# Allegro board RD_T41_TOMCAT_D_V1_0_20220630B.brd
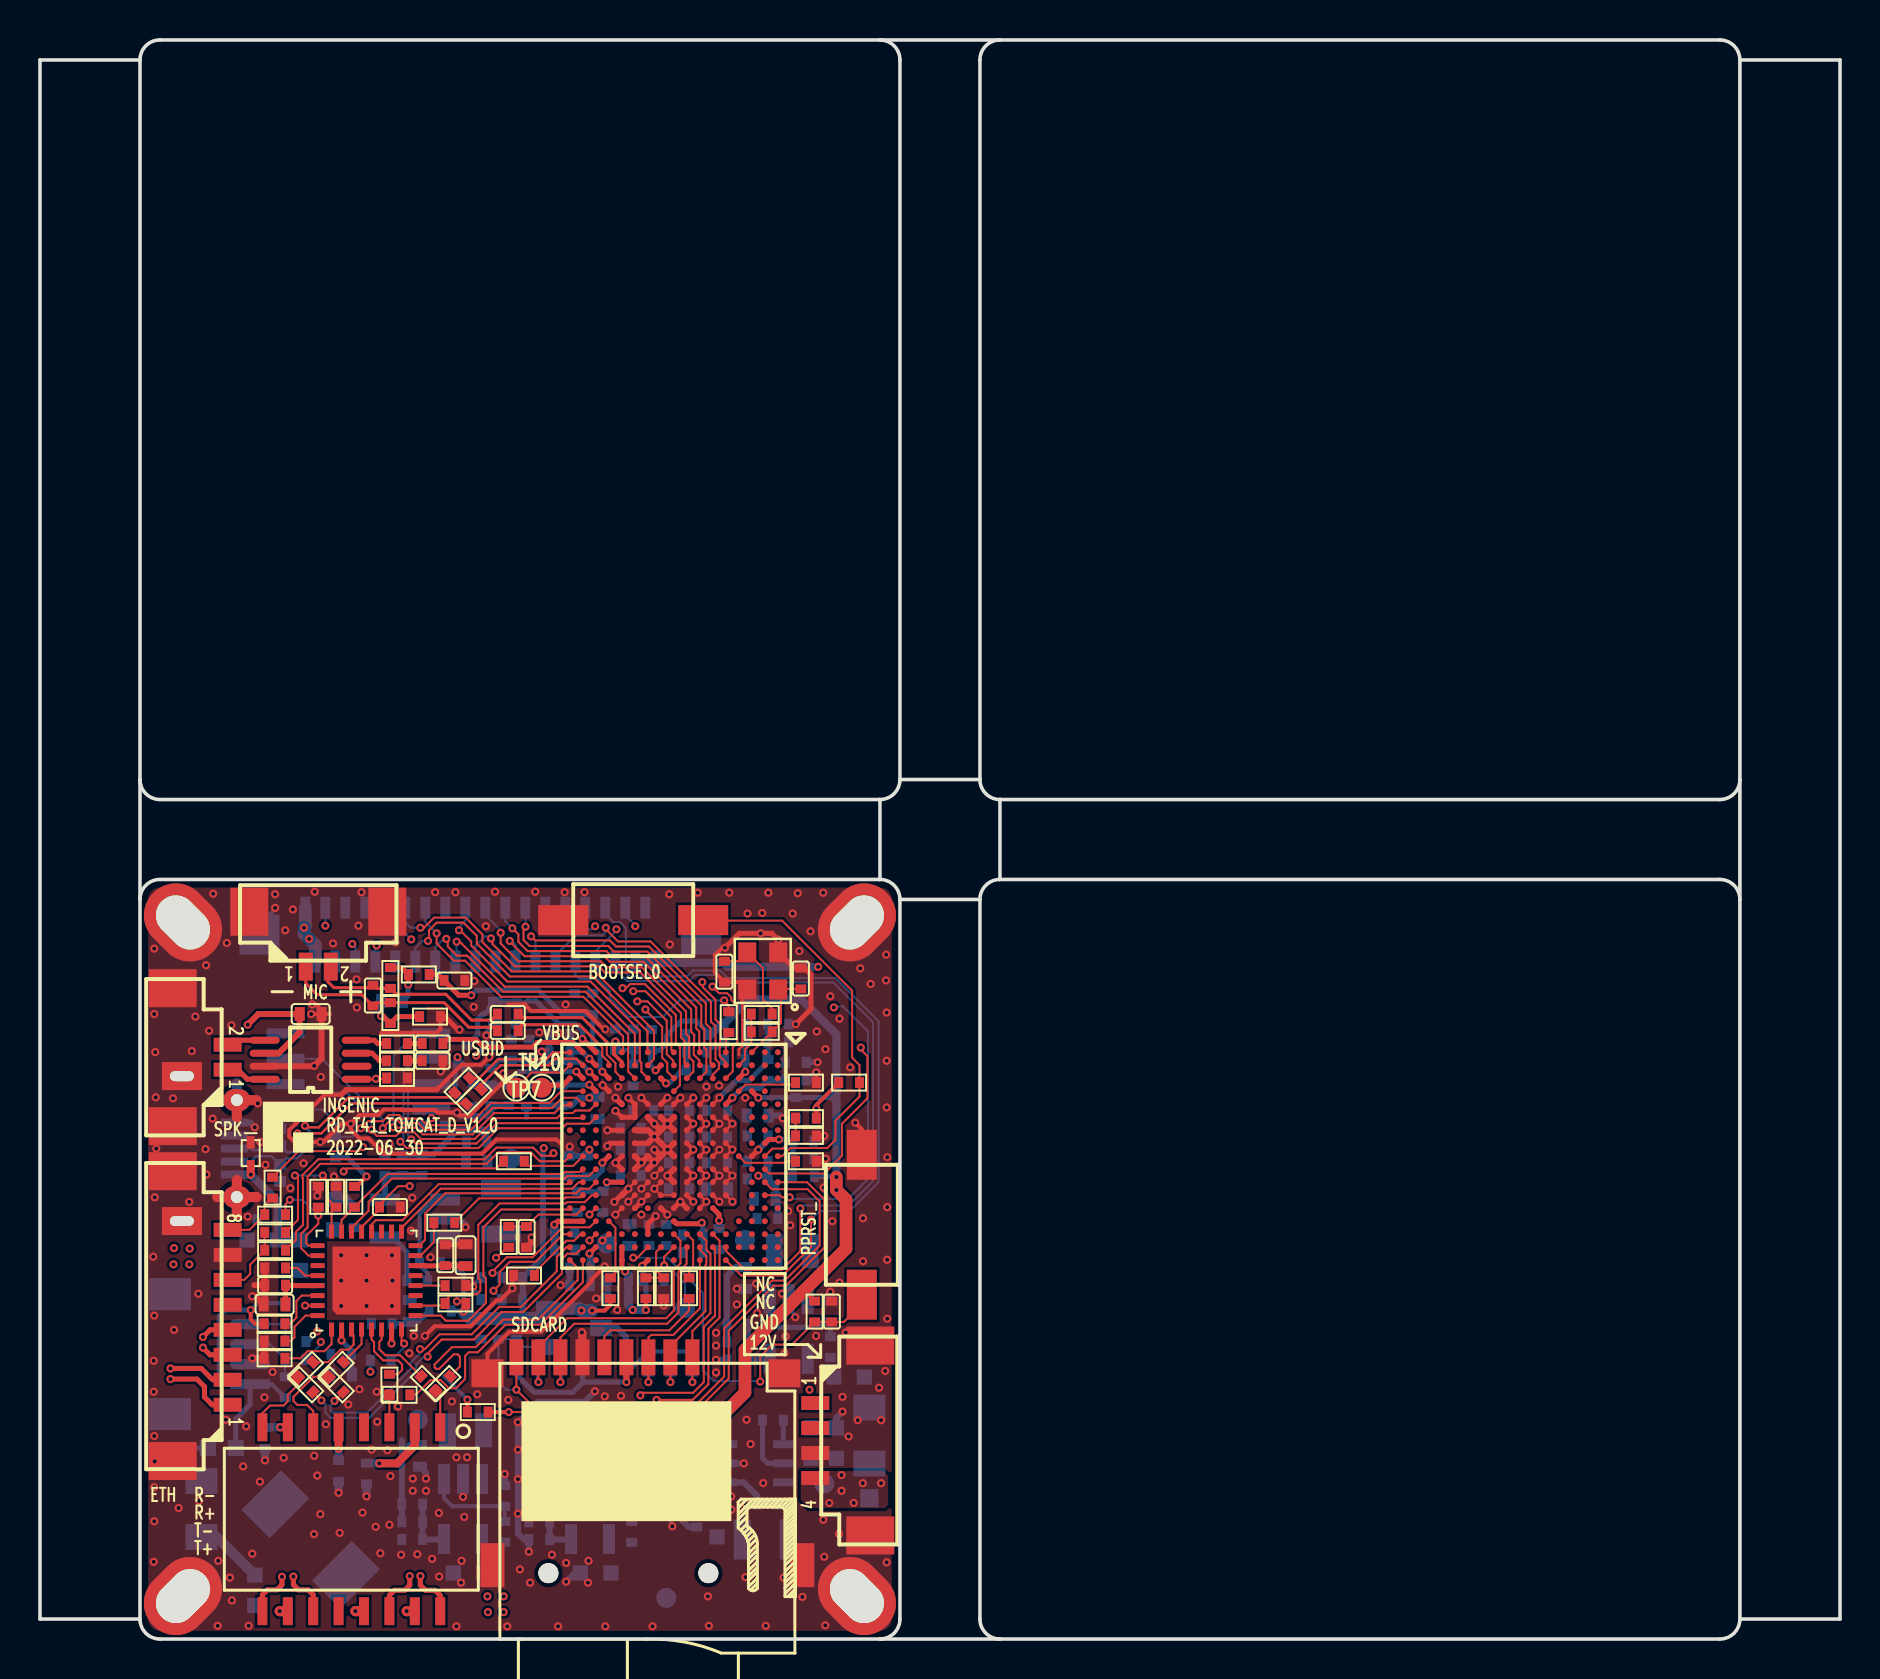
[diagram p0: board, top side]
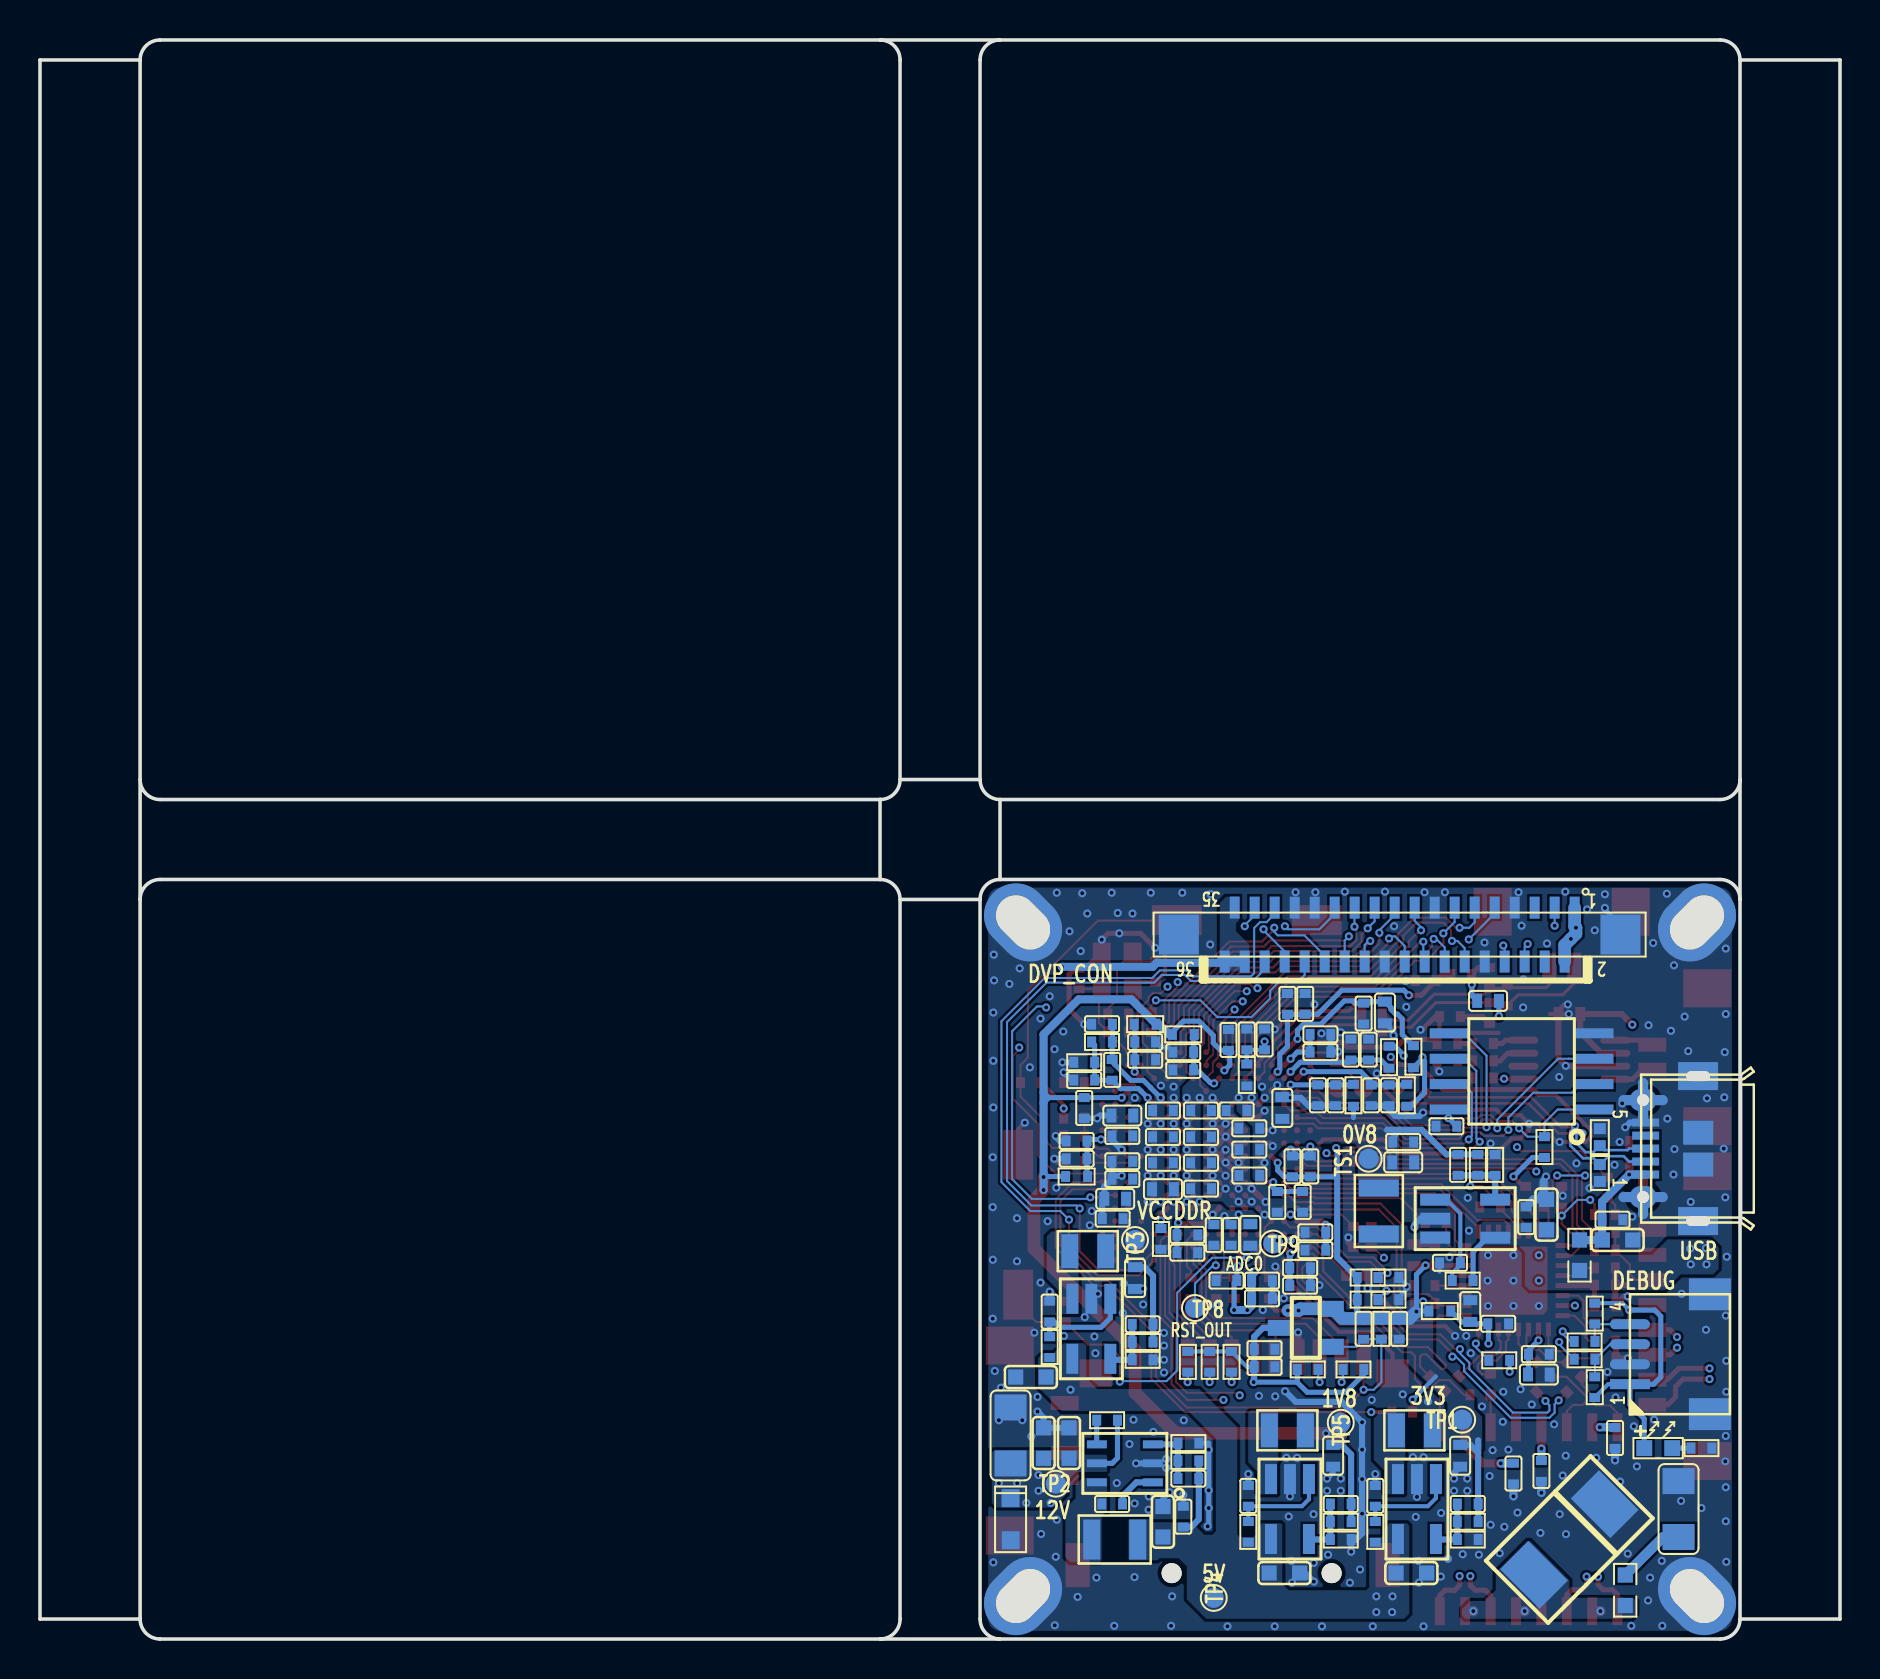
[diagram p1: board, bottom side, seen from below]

Outline 90.01 x 80 mm; copper layers: TOP, L2_GND, L3_PWR, BOTTOM. Coordinates in mm from the lower left corner of the outline.
Outline path: 5,1 0,1 0,79 5,79 ; 5,1 5,37 ; 5,1 arc(5.29,0.29) 6,0 42,0 ; 5,79 5,43 ; 5,79 arc(5.29,79.71) 6,80 42,80 ; 5,43 5,37 ; 5,43 arc(5.29,42.29) 6,42 42,42 ; 5,37 arc(5.29,37.71) 6,38 42,38 ; 42,42 42,38 ; 42,42 arc(42.71,42.29) 43,43 ; 42,38 arc(42.71,37.71) 43,37 ; 42,80 arc(42.71,79.71) 43,79 43,43 ; 42,80 48,80 ; 43,37 43,1 arc(42.71,0.29) 42,0 ; 43,37 47,37 ; 42,0 48,0 ; 48,0 arc(47.29,0.29) 47,1 47,37 ; 48,0 84,0 arc(84.71,0.29) 85,1 ; 43,43 47,43 ; 48,80 arc(47.29,79.71) 47,79 47,43 ; 48,80 84,80 arc(84.71,79.71) 85,79 ; 47,43 arc(47.29,42.29) 48,42 ; 47,37 arc(47.29,37.71) 48,38 ; 48,38 48,42 ; 48,38 84,38 arc(84.71,37.71) 85,37 ; 48,42 48.01,41.99 ; 48,42 84,42 arc(84.71,42.29) 85,43 ; 85,79 85,43 ; 85,79 90.01,79 90.01,1 85,1 ; 85,37 85,43 ; 85,37 85,1

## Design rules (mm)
net group DP_RD: nets RD_N RD_P
net group DP_TD: nets TD_N TD_P
net group DP_TRXN0: nets TRXN0 TRXP0
net group DP_TRXN1: nets TRXN1 TRXP1
net group MDI_R: nets MDI_RN MDI_RP
net group MDI_T: nets MDI_TN MDI_TP
net group MICNL: nets MICNL N16707590
net group MICPL: nets MICPL N16712105
net group RJ45_RX: nets RX+ RX-
net group RJ45_TX: nets TX+ TX-
net group USB0PN: nets N16707578 USB0PN
net group USB0PP: nets N16707574 USB0PP
net group POW: nets AVDD33 CSI_VCC08 CSI_VCC18 DDR_VREF DVDD1V2OUT MICBIAS USB_AVD08 USB_AVD18 USB_AVD33 VDDMSC0
nets with their own width: min track width 0.203; nets GND VCC_3V3

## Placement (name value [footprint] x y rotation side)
C1  22uF/25V-1206  [C1206]  41.47 10.19 90 bottom
C2  10uF/10V-0603  [C0603]  21.43 3.3 180 bottom
C3  100nF/10V  [C0402]  23.24 7.16 90 bottom
C4  22pF/50V  [C0402]  18.61 6.76 0 bottom
C5  10uF/6.3V  [C0402_E]  19 9.17 270 bottom
C6  10nF/25V  [C0402]  36.39 6.76 0 bottom
C7  10uF/25V-0603  [C0603]  39.82 9.8 90 bottom
C8  10uF/25V-0603  [C0603]  38.55 9.8 90 bottom
C9  22pF/50V  [C0402]  34.87 15.75 0 bottom
C10  22pF/50V  [C0402]  32.58 8.03 0 bottom
C11  10uF/10V-0603  [C0603]  33.85 5.87 90 bottom
C12  100nF/10V  [C0402]  32.84 6.12 90 bottom
C13  10uF/10V-0603  [C0603]  40.46 13.11 0 bottom
C14  100nF/10V  [C0402]  39.52 16.38 90 bottom
C15  10uF/6.3V  [C0402_E]  35.25 18.06 270 bottom
C16  22pF/50V  [C0402]  24.96 6.76 0 bottom
C17  10uF/6.3V  [C0402_E]  25.35 9.17 270 bottom
C18  10uF/10V-0603  [C0603]  27.78 3.3 180 bottom
C19  10uF/10V-0603  [C0603]  14.68 21.23 90 bottom
C20  100nF/10V  [C0402]  15.69 21.11 90 bottom
C21  10uF/6.3V  [C0402_E]  21.84 23.85 180 bottom
C22  100nF/6.3V  [C0402]  21.84 24.87 180 bottom
C23  22pF/50V  [C0402]  19.1 23.72 90 bottom
C24  100nF/6.3V  [C0402]  35.89 23.01 0 bottom
C25  10uF/6.3V  [C0402_E]  36.24 22.02 0 bottom
C26  100nF/6.3V  [C0402]  35.89 23.9 0 bottom
C27  100nF/6.3V  [C0402]  35.89 25.17 0 bottom
C28  10uF/6.3V  [C0402_E]  35.89 26.19 0 bottom
C29  1uF/6.3V  [C0402]  32.84 28.47 0 bottom
C30  1uF/6.3V  [C0402]  34.74 29.87 180 bottom
C31  1uF/6.3V  [C0402]  26.87 21.87 270 bottom
C32  10uF/6.3V  [C0402_E]  33.85 22.5 180 bottom
C33  100nF/6.3V  [C0402]  36.37 21.03 0 bottom
C34  10nF/6.3V  [C0402]  33.85 23.83 180 bottom
C35  100nF/6.3V  [C0402]  33.85 25.12 180 bottom
C36  1uF/6.3V  [C0402]  22.55 27.2 270 bottom
C37  100nF/6.3V  [C0402]  33.85 26.44 180 bottom
C38  1uF/6.3V  [C0402]  28.9 17.04 180 bottom
C39  1uF/6.3V  [C0402]  27.38 23.65 90 bottom
C40  100nF/6.3V  [C0402]  36.39 28.47 90 bottom
C41  4.7uF/6.3V  [C0402]  36.9 30.76 0 bottom
C42  100nF/6.3V  [C0402]  37.79 27.97 180 bottom
C43  10uF/6.3V  [C0402_E]  27.89 26.57 90 bottom
C44  10uF/6.3V  [C0402_E]  29.49 20.22 270 bottom
C45  100nF/6.3V  [C0402]  29.54 24.49 0 bottom
C46  100nF/6.3V  [C0402]  29.54 25.55 0 bottom
C47  100nF/6.3V  [C0402]  30.17 26.44 0 bottom
C48  100nF/6.3V  [C0402]  31.95 26.44 180 bottom
C49  100nF/6.3V  [C0402]  31.95 23.83 180 bottom
C50  100nF/6.3V  [C0402]  31.95 22.53 180 bottom
C51  1uF/6.3V  [C0402]  32.64 20.22 180 bottom
C52  10nF/6.3V  [C0402]  31.95 25.12 180 bottom
C53  10nF/6.3V  [C0402]  31.31 20.22 270 bottom
C54  1uF/6.3V  [C0402]  38.17 24.03 0 bottom
C55  10nF/6.3V  [C0402]  29.54 23.19 0 bottom
C56  10uF/6.3V  [C0402_E]  17.6 31.93 0 bottom
C57  1uF/6.3V  [C0402]  26.23 19.46 0 bottom
C58  100nF/6.3V  [C0402]  26.23 20.35 0 bottom
C59  1uF/6.3V  [C0402]  27 18.57 180 bottom
C60  100nF/6.3V  [C0402]  27 17.68 180 bottom
C61  100nF/6.3V  [C0402]  24.33 20.12 90 top
C62  100nF/10V  [C0402]  29.59 7.16 90 bottom
C63  100nF/6.3V  [C0402]  34.74 28.98 180 bottom
C64  100nF/6.3V  [C0402]  38.17 24.92 0 bottom
C65  100nF/6.3V  [C0402]  23.82 31.29 270 bottom
C66  10uF/6.3V  [C0402_E]  22.75 31.34 270 bottom
C67  100nF/6.3V  [C0402]  23.39 31.27 180 top
C68  100nF/6.3V  [C0402]  23.39 30.43 180 top
C69  4.7uF/6.3V  [C0402]  25.98 30.25 180 bottom
C70  100nF/6.3V  [C0402]  25.98 29.36 180 bottom
C71  1uF/6.3V  [C0402]  25.22 27.2 270 bottom
C72  100nF/6.3V  [C0402]  26.11 27.2 270 bottom
C73  100nF/6.3V  [C0402]  23.44 27.2 270 bottom
C74  1uF/6.3V  [C0402]  23.57 29.49 90 bottom
C75  100nF/6.3V  [C0402]  24.46 29.49 90 bottom
C76  100nF/6.3V  [C0402]  28.9 17.93 180 bottom
C78  4.7uF/6.3V  [C0402]  26.74 31.78 90 bottom
C79  100nF/6.3V  [C0402]  27.63 31.78 90 bottom
C80  12pF/50V  [C0402]  38.05 33.05 270 top
C81  100nF/6.3V  [C0402]  19.68 25.65 180 bottom
C82  12pF/50V  [C0402]  34.22 33.39 90 top
C83  100nF/6.3V  [C0402]  30.68 17.93 0 bottom
C84  1uF/6.3V  [C0402]  29.66 30 90 bottom
C85  100nF/6.3V  [C0402]  28.77 30 90 bottom
C86  100nF/6.3V  [C0402]  32.84 29.36 0 bottom
C87  100nF/6.3V  [C0402]  30.58 29.97 90 bottom
C88  100nF/6.3V  [C0402]  37.79 26.57 270 bottom
C89  100nF/6.3V  [C0402]  26.49 23.65 90 bottom
C90  100nF/6.3V  [C0402]  32.64 19.33 180 bottom
C91  4.7uF/6.3V  [C0402]  22.04 15.52 270 bottom
C92  100nF/6.3V  [C0402]  23.82 15.52 270 bottom
C93  4.7uF/6.3V  [C0402]  28.77 14.5 180 bottom
C94  100nF/6.3V  [C0402]  28.77 13.61 180 bottom
C95  10uF/10V-0603  [C0603]  11.12 19.96 180 bottom
C96  100nF/25V  [C0402]  16.33 8.28 90 bottom
C97  100nF/25V  [C0402]  14.93 8.41 90 bottom
C98  100nF/25V  [C0402]  11.25 10.06 90 bottom
C99  10uF/6.3V  [C0402_E]  21.28 19.2 90 top
C100  100nF/6.3V  [C0402]  20.27 19.2 90 top
C101  10uF/6.3V  [C0402_E]  15.06 13.23 180 bottom
C102  100nF/6.3V  [C0402]  15.06 14.25 180 bottom
C103  10uF/6.3V  [C0402_E]  11.73 16.74 180 top
C104  100nF/6.3V  [C0402]  11.76 17.7 180 top
C105  100pF/50V  [C0402]  16.65 32.19 90 top
C106  3.3nF/50V  [C0402]  19.63 28.93 0 top
C107  3.3nF/50V  [C0402]  19.63 29.79 0 top
C108  10uF/6.3V  [C0402_E]  13.53 31.27 0 top
C110  4.7uF/6.3V  [C0402]  20.72 32.94 0 top
C111  1uF/6.3V  [C0402]  39.59 16.38 90 top
C112  100nF/10V  [C0402]  19.5 18.82 0 bottom
C113  100nF/6.3V  [C0402]  30.45 20.22 270 bottom
C114  100nF/6.3V  [C0402]  28.14 21.87 270 bottom
C119  100nF/10V  [C0402]  11.38 20.98 180 bottom
C125  100nF/6.3V  [C0402]  17.5 21.62 0 top
C126  1nF/2KV-1206  [C1206]  8.07 6.5 270 bottom
C127  10uF/6.3V  [C0402_E]  18.49 16.41 90 bottom
C128  100nF/6.3V  [C0402]  17.09 15.77 180 bottom
D1  BZT52C12S  [SOD323]  41.47 5.99 90 bottom
D2  LED Red  [D0603_LED]  9.09 9.55 180 bottom
D3  LXES1UTAA1-157  [DFN1006]  12.01 25.11 90 bottom
D4  P3100SC  [SMB]  13.53 4.98 315 bottom
D5  LXES1UTAA1-157  [DFN1006]  12.01 23.32 270 bottom
D6  ESD5451X  [ESD0402]  10.54 24.31 270 top
FB1  1000ohm/250mA  [FB0402]  38.17 23.14 0 bottom
FB2  1000ohm/250mA  [FB0402]  20.01 16.41 0 bottom
FB3  1000ohm/250mA  [FB0402]  34.74 30.76 180 bottom
FB4  1000ohm/250mA  [FB0402]  24.33 27.2 90 bottom
FB5  1000ohm/250mA  [FB0402]  21.66 27.2 90 bottom
FB6  1000ohm/250mA  [FB0402]  22.55 29.11 270 bottom
FB7  1000ohm/250mA  [FB0402]  21.33 29.13 90 bottom
FB8  1000ohm/250mA  [FB0402]  29.66 28.22 270 bottom
FB9  1000ohm/250mA  [FB0402]  32.84 30.25 0 bottom
H1  MHOBL  [MHOLE_3D0X2D0]  7.15 35.85 90 top
H2  MHOBL  [MHOLE_3D0X2D0]  40.85 2.15 90 top
H3  MHOBL  [MHOLE_3D0X2D0]  7.15 2.15 0 top
H4  MHOBL  [MHOLE_3D0X2D0]  40.85 35.85 0 top
J1  CON4 1.25mm LT  [CON4-1D25-LT]  40.97 9.93 90 top
J2  MICROSD_TF  [TFCARD]  30.37 13.9 0 top
J3  CON36 0.5mm LT  [FPC-CON36-0D5-LT]  22.02 35.24 0 bottom
J4  MICRO USB  [MICROUSB_B_NJ5P]  9.72 24.54 270 bottom
J5  CON8 1.25mm LT  [CON8-1D25-LT]  7.18 16.15 270 top
J6  CON2 1.25mm LT  [CON2-1D25-LT]  13.92 35.84 180 top
J7  CON2 1.25mm LT  [CON2-1D25-LT]  7.18 29.11 270 top
J8  CON4 1.0mm WT  [CON4-1D0-WT]  8 14.25 90 bottom
L1  2.2uH/1.3A-2016  [L2016]  21.28 10.44 0 bottom
L2  4.7uH/1.4A-2520  [L2520]  36.27 4.98 180 bottom
L3  2.2uH/1.3A-2016  [L2016]  37.61 19.41 0 bottom
L4  2.2uH/2.2A-2520  [L2520]  23.06 21.41 90 bottom
L5  2.2uH/1.3A-2016  [L2016]  27.63 10.44 0 bottom
NOREF  -  []  12.87 25.59 0 top
NOREF#2  -  []  5.32 37.73 0 top
NOREF#3  -  []  41.27 158.18 0 top
NOREF#4  -  []  6 0 90 top
NOREF#5  -  []  5 1 0 top
NOREF#6  -  []  -189.11 -122.58 0 top
NOREF#7  -  []  -41.62 136.12 0 top
Q1  WPM3401  [SOT23]  26.71 15.57 90 bottom
R1  100K  [R0402]  23.24 5.36 90 bottom
R2  150K/1%  [R0402]  18.61 5.87 180 bottom
R3  33.2K/1%  [R0402]  18.61 4.98 0 bottom
R4  100K  [R0402]  36.65 10.95 0 bottom
R5  100K  [R0402]  39.52 14.61 90 bottom
R6  200K/1%  [R0402]  32.58 8.92 0 bottom
R7  150K/1%  [R0402]  34.87 14.86 180 bottom
R8  27K/1%  [R0402]  32.58 9.8 0 bottom
R9  100K/1%  [R0402]  34.87 13.97 0 bottom
R10  100K  [R0402]  18.87 17.93 0 bottom
R11  100K  [R0402]  29.59 5.36 90 bottom
R13  2.2R/1%  [R0402]  13.28 12.73 135 top
R14  1K  [R0402]  6.93 9.55 180 bottom
R15  100K/1%  [R0402]  36.9 29.87 180 bottom
R16  240R/1%  [R0402]  33.96 20.02 270 bottom
R17  100K/1%  [R0402]  37.79 28.85 180 bottom
R18  240R/1%  [R0402]  38.3 23.9 0 top
R19  33R  [R0402]  20.21 20.83 180 top
R20  1K  [R0402]  30.3 17.55 90 top
R21  33R  [R0402]  38.3 27.84 180 top
R22  10K  [R0402]  14.78 24.61 270 bottom
R23  1M  [R0402]  36.09 30.38 0 top
R24  33R  [R0402]  36.09 31.27 180 top
R25  33R  [R0402]  32.46 17.55 90 top
R26  2.49K/1%  [R0402]  24.2 18.19 180 top
R27  1K  [R0402]  22.58 16.98 0 bottom
R28  2.2R/1%  [R0402]  14.8 12.73 135 top
R29  100K  [R0402]  26.62 13.49 180 bottom
R30  100K  [R0402]  30.43 13.87 270 bottom
R31  100K  [R0402]  24.33 13.49 0 bottom
R32  100K  [R0402]  32.61 13.87 270 bottom
R33  100K  [R0402]  31.52 13.87 270 bottom
R34  100K  [R0402]  22.93 15.52 270 bottom
R35  2.2R/1%  [R0402]  13.28 13.49 225 top
R36  2.2R/1%  [R0402]  14.8 13.49 225 top
R37  10K  [R0402]  15.72 22.12 270 top
R39  2.2R/1%  [R0402]  17.47 12.73 270 top
R40  2.2R/1%  [R0402]  19.42 12.78 315 top
R41  2.49K/1%  [R0402]  11.73 14.05 180 top
R44  10K  [R0402]  20.77 16.79 180 top
R46  10K  [R0402]  11.76 18.57 0 top
R47  0R  [R0402]  11.73 14.91 0 top
R48  1.1K  [R0402]  17.52 31.32 270 top
R49  1.1K  [R0402]  19.5 31.14 180 top
R50  10K  [R0402]  17.85 28.07 0 top
R51  1.1K  [R0402]  17.52 33.07 270 top
R52  68K/1%  [R0402]  17.85 28.93 0 top
R53  68K/1%  [R0402]  17.85 29.79 0 top
R55  100K  [R0402]  40.46 27.84 180 top
R56  100K  [R0402]  38.3 26.06 0 top
R57  10K  [R0402]  12.26 12.6 90 bottom
R58  10K  [R0402]  12.26 16.28 270 bottom
R59  100K  [R0402]  38.3 25.17 180 top
R60  33R  [R0402]  12.77 14.88 0 bottom
R61  33R  [R0402]  12.77 14 0 bottom
R62  100K  [R0402]  38.73 16.38 270 top
R63  100K/1%  [R0402]  18.11 23.72 90 bottom
R64  300K/1%  [R0402]  17.24 23.72 90 bottom
R65  10K  [R0402]  23.62 18.08 0 bottom
R66  33R  [R0402]  23.69 23.9 0 top
R67  33R  [R0402]  34.44 30.86 270 top
R68  10K  [R0402]  28.52 17.55 270 top
R69  10K  [R0402]  23.62 16.98 0 bottom
R70  10K  [R0402]  21.89 11.35 180 top
R71  1K  [R0402]  22.58 18.08 0 bottom
R72  2.2R/1%  [R0402]  17.98 12.22 180 top
R73  2.2R/1%  [R0402]  20.14 12.78 225 top
R74  300R  [R0402]  11.76 19.46 180 top
R75  300R  [R0402]  11.63 22.58 270 top
R76  300R  [R0402]  11.76 21.23 0 top
R77  300R  [R0402]  11.76 20.35 0 top
R78  1K  [R0402]  31.19 17.55 90 top
R81  1.1K  [R0402]  18.94 33.25 180 top
R85  0R-0603  [R0603]  13.03 19.2 270 bottom
R86  200K/1%  [R0402]  24.96 5.87 180 bottom
R87  10K  [R0402]  17.04 13.94 0 bottom
R88  10K  [R0402]  14.8 22.12 270 top
R89  10K  [R0402]  13.92 22.12 270 top
R92  10K  [R0402]  20.77 17.68 180 top
R93  75R/1%-0603  [R0603]  10.74 2.44 270 bottom
R94  10K  [R0402]  11.73 15.77 180 top
R98  100K/1%  [R0402]  24.96 4.98 0 bottom
R99  0R  [R0402]  23.44 20.12 270 top
R100  2.2R/5%  [R0402]  21.11 27.7 225 top
R101  2.2R/5%  [R0402]  21.69 27.14 225 top
SW1  KEY2_SMD  [SW2_SMD]  29.66 35.97 0 top
SW2  KEY2_SMD  [SW2_SMD]  41.09 20.73 270 top
TP1  1mm_SMD  [TEST_SMD]  18.89 10.97 180 bottom
TP2  1mm_SMD  [TEST_SMD]  39.21 7.77 180 bottom
TP3  1mm_SMD  [TEST_SMD]  35.25 19.96 90 bottom
TP4  1mm_SMD  [TEST_SMD]  31.31 2.06 90 bottom
TP5  1mm_SMD  [TEST_SMD]  24.96 10.82 90 bottom
TP7  1mm_SMD  [TEST_SMD]  23.82 27.58 0 top
TP8  1mm_SMD  [TEST_SMD]  32.25 16.56 180 bottom
TP9  1mm_SMD  [TEST_SMD]  28.34 19.79 180 bottom
TP10  1mm_SMD  [TEST_SMD]  25.09 27.58 0 top
TS1  1mm_SMD  [TEST_SMD]  23.57 24.03 90 bottom
U1  LN5058  [SOT23-5]  21.15 6.5 0 bottom
U2  ETA8120  [SOT23-6]  35.76 8.79 0 bottom
U3  LN5058  [SOT23-5]  37.44 15.52 0 bottom
U4  LN5058  [SOT23-5]  27.5 6.5 0 bottom
U5  ETA3409  [SOT23-5]  18.74 21.03 270 bottom
U6  T41 BGA232  [BGA232_0D65_T41]  31.7 24.16 270 top
U7  GD25Q127CSIG  [WSOP8_1D27]  15.92 28.4 0 bottom
U8  SZ18201  [QFN32_0D5_SZ18201]  16.33 17.93 90 top
U9  FC1680C  [QFP16_1D27]  15.57 5.99 270 top
U10  CS8302M  [MSOP8_0D65]  13.53 28.98 90 top
Y1  24M 2016  [CRY_2D5X2D0]  36.14 33.43 90 top

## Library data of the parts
C1-C66 C69-C76 C78-C108 C110-C114 C119 C125-C128 = CAP
C67 C68 = CAP: signal model: CAP_C0402_100NF/6.3V_100nF/6.3V
D1 = DIODE_WY
D2 = LED_1
D3 D5 D6 = ESD
D4 = P3100
FB1-FB9 = BEAD
H1-H4 = MHOLE1
J1 = CON_4x1
J2 = MMC_SD
J3 = FPCCON_18X2
J4 = MICROUSB_0
J5 = CON_8x1
J6 J7 = CON_2X1
J8 = CON_4X1
L1-L5 = INDUCTOR
Q1 = P_MOS
R1-R11 R13-R37 R39-R41 R44 R46-R53 R55-R78 R81 R85-R89 R92-R94 R98 R99 = RES
R100 R101 = RES: signal model: RES_R0402_2.2R/5%_2.2R/5%
SW1 SW2 = PUSHBUTTON
TP1-TP5 TP7-TP10 TS1 = TP
U1 U3-U5 = SY8088
U2 = SY8120
U6 = T41_BGA232
U7 = SPI_NOR
U8 = SZ18201
U9 = FC1680C
U10 = CS8302
Y1 = XTAL_P4

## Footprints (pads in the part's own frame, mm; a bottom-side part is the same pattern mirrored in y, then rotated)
BGA232_0D65_T41
  round 0.3 smd: A1(-5.2,5.2) A2(-4.55,5.2) A3(-3.9,5.2) A5(-2.6,5.2) A7(-1.3,5.2) A9(0,5.2) A11(1.3,5.2) A13(2.6,5.2) A15(3.9,5.2) A16(4.55,5.2) A17(5.2,5.2) B1(-5.2,4.55) B2(-4.55,4.55) B3(-3.9,4.55) B4(-3.25,4.55) B5(-2.6,4.55) B6(-1.95,4.55) B7(-1.3,4.55) B8(-0.65,4.55) B9(0,4.55) B10(0.65,4.55) B11(1.3,4.55) B12(1.95,4.55) B13(2.6,4.55) B14(3.25,4.55) B15(3.9,4.55) B16(4.55,4.55) B17(5.2,4.55) C1(-5.2,3.9) C2(-4.55,3.9) C3(-3.9,3.9) C4(-3.25,3.9) C5(-2.6,3.9) C6(-1.95,3.9) C7(-1.3,3.9) C8(-0.65,3.9) C9(0,3.9) C10(0.65,3.9) C11(1.3,3.9) C12(1.95,3.9) C13(2.6,3.9) C14(3.25,3.9) C15(3.9,3.9) C16(4.55,3.9) C17(5.2,3.9) D2(-4.55,3.25) D3(-3.9,3.25) D4(-3.25,3.25) D9(0,3.25) D14(3.25,3.25) D15(3.9,3.25) D16(4.55,3.25) E1(-5.2,2.6) E2(-4.55,2.6) E3(-3.9,2.6) E5(-2.6,2.6) E6(-1.95,2.6) E7(-1.3,2.6) E8(-0.65,2.6) E9(0,2.6) E10(0.65,2.6) E11(1.3,2.6) E12(1.95,2.6) E15(3.9,2.6) E16(4.55,2.6) E17(5.2,2.6) F2(-4.55,1.95) F3(-3.9,1.95) F5(-2.6,1.95) F6(-1.95,1.95) F7(-1.3,1.95) F8(-0.65,1.95) F9(0,1.95) F10(0.65,1.95) F11(1.3,1.95) F12(1.95,1.95) F13(2.6,1.95) F15(3.9,1.95) F16(4.55,1.95) G1(-5.2,1.3) G2(-4.55,1.3) G3(-3.9,1.3) G5(-2.6,1.3) G6(-1.95,1.3) G7(-1.3,1.3) G8(-0.65,1.3) G9(0,1.3) G10(0.65,1.3) G11(1.3,1.3) G12(1.95,1.3) G13(2.6,1.3) G15(3.9,1.3) G16(4.55,1.3) G17(5.2,1.3) H2(-4.55,0.65) H3(-3.9,0.65) H5(-2.6,0.65) H6(-1.95,0.65) H7(-1.3,0.65) H8(-0.65,0.65) H9(0,0.65) H10(0.65,0.65) H11(1.3,0.65) H12(1.95,0.65) H13(2.6,0.65) H15(3.9,0.65) H16(4.55,0.65) J1(-5.2,0) J2(-4.55,0) J3(-3.9,0) J4(-3.25,0) J5(-2.6,0) J6(-1.95,0) J7(-1.3,0) J8(-0.65,0) J9(0,0) J10(0.65,0) J11(1.3,0) J12(1.95,0) J13(2.6,0) J14(3.25,0) J15(3.9,0) J16(4.55,0) J17(5.2,0) K2(-4.55,-0.65) K3(-3.9,-0.65) K5(-2.6,-0.65) K6(-1.95,-0.65) K7(-1.3,-0.65) K8(-0.65,-0.65) K9(0,-0.65) K10(0.65,-0.65) K11(1.3,-0.65) K12(1.95,-0.65) K13(2.6,-0.65) K15(3.9,-0.65) K16(4.55,-0.65) L1(-5.2,-1.3) L2(-4.55,-1.3) L3(-3.9,-1.3) L5(-2.6,-1.3) L6(-1.95,-1.3) L7(-1.3,-1.3) L8(-0.65,-1.3) L9(0,-1.3) L10(0.65,-1.3) L11(1.3,-1.3) L12(1.95,-1.3) L13(2.6,-1.3) L15(3.9,-1.3) L16(4.55,-1.3) L17(5.2,-1.3) M2(-4.55,-1.95) M3(-3.9,-1.95) M5(-2.6,-1.95) M6(-1.95,-1.95) M7(-1.3,-1.95) M8(-0.65,-1.95) M9(0,-1.95) M10(0.65,-1.95) M11(1.3,-1.95) M12(1.95,-1.95) M13(2.6,-1.95) M15(3.9,-1.95) M16(4.55,-1.95) N1(-5.2,-2.6) N2(-4.55,-2.6) N3(-3.9,-2.6) N5(-2.6,-2.6) N6(-1.95,-2.6) N7(-1.3,-2.6) N8(-0.65,-2.6) N9(0,-2.6) N10(0.65,-2.6) N11(1.3,-2.6) N12(1.95,-2.6) N13(2.6,-2.6) N15(3.9,-2.6) N16(4.55,-2.6) N17(5.2,-2.6) P2(-4.55,-3.25) P3(-3.9,-3.25) P4(-3.25,-3.25) P9(0,-3.25) P14(3.25,-3.25) P15(3.9,-3.25) P16(4.55,-3.25) R1(-5.2,-3.9) R2(-4.55,-3.9) R3(-3.9,-3.9) R4(-3.25,-3.9) R5(-2.6,-3.9) R6(-1.95,-3.9) R7(-1.3,-3.9) R8(-0.65,-3.9) R9(0,-3.9) R10(0.65,-3.9) R11(1.3,-3.9) R12(1.95,-3.9) R13(2.6,-3.9) R14(3.25,-3.9) R15(3.9,-3.9) R16(4.55,-3.9) R17(5.2,-3.9) T1(-5.2,-4.55) T2(-4.55,-4.55) T3(-3.9,-4.55) T4(-3.25,-4.55) T5(-2.6,-4.55) T6(-1.95,-4.55) T7(-1.3,-4.55) T8(-0.65,-4.55) T9(0,-4.55) T10(0.65,-4.55) T11(1.3,-4.55) T12(1.95,-4.55) T13(2.6,-4.55) T14(3.25,-4.55) T15(3.9,-4.55) T16(4.55,-4.55) T17(5.2,-4.55) U1(-5.2,-5.2) U2(-4.55,-5.2) U3(-3.9,-5.2) U5(-2.6,-5.2) U7(-1.3,-5.2) U9(0,-5.2) U11(1.3,-5.2) U13(2.6,-5.2) U15(3.9,-5.2) U16(4.55,-5.2) U17(5.2,-5.2)
C0402
  rect 0.45x0.55 smd: 1(-0.52,0) 2(0.52,0)
C0402_E
  rect 0.5x0.7 smd: 1(-0.545,0) 2(0.545,0)
C0603
  rect 0.76x0.76 smd: 1(-0.762,0) 2(0.762,0)
C1206
  rect 1.3x1.6 smd: 1(-1.4,0) 2(1.4,0)
CON2-1D25-LT
  rect 0.7x1.4 smd: 1(0.625,2.2) 2(-0.625,2.2)
  rect 1.9x2.4 smd: 3(-3.45,-0.55) 4(3.45,-0.55)
CON4-1D0-WT
  rect 0.5x2 smd: 1(-1.5,2.5)
  oval 0.5x2 smd: 2(-0.5,2.5) 3(0.5,2.5) 4(1.5,2.5)
  rect 1.6x2.1 smd: 5(3,-1.5) 6(-3,-1.5)
CON4-1D25-LT
  rect 0.7x1.4 smd: 1(1.875,2.2) 2(0.625,2.2) 3(-0.625,2.2) 4(-1.875,2.2)
  rect 1.9x2.4 smd: 5(-4.75,-0.55) 6(4.75,-0.55)
CON8-1D25-LT
  rect 0.7x1.4 smd: 1(4.435,2.2) 2(3.185,2.2) 3(1.935,2.2) 4(0.685,2.2) 5(-0.565,2.2) 6(-1.815,2.2) 7(-3.065,2.2) 8(-4.315,2.2)
  rect 1.9x2.4 smd: 9(-7.25,-0.55) 10(7.25,-0.55)
CRY_2D5X2D0
  rect 1x0.9 smd: 1(-0.925,-0.775) 2(0.925,-0.775) 3(0.925,0.775) 4(-0.925,0.775)
D0603_LED
  rect 0.8x0.8 smd: 1(-0.7,0) 2(0.7,0)
DFN1006
  rect 0.55x0.6 smd: 1(0.425,0) 2(-0.425,0)
ESD0402
  rect 0.62x0.4 smd: 1(-0.54,0)
  rect 0.5x0.4 smd: 2(0.6,0)
FB0402
  rect 0.45x0.55 smd: 1(-0.55,0) 2(0.55,0)
FPC-CON36-0D5-LT
  rect 0.5x1.1 smd: 1(-8.75,-1.35) 2(-8.25,1.35) 3(-7.75,-1.35) 4(-7.25,1.35) 5(-6.75,-1.35) 6(-6.25,1.35) 7(-5.75,-1.35) 8(-5.25,1.35) 9(-4.75,-1.35) 10(-4.25,1.35) 11(-3.75,-1.35) 12(-3.25,1.35) 13(-2.75,-1.35) 14(-2.25,1.35) 15(-1.75,-1.35) 16(-1.25,1.35) 17(-0.75,-1.35) 18(-0.25,1.35) 19(0.25,-1.35) 20(0.75,1.35) 21(1.25,-1.35) 22(1.75,1.35) 23(2.25,-1.35) 24(2.75,1.35) 25(3.25,-1.35) 26(3.75,1.35) 27(4.25,-1.35) 28(4.75,1.35) 29(5.25,-1.35) 30(5.75,1.35) 31(6.25,-1.35) 32(6.75,1.35) 33(7.25,-1.35) 34(7.75,1.35) 35(8.25,-1.35) 36(8.75,1.35)
  rect 2x2 smd: 37(-11.04,0) 38(11.04,0)
L2016
  rect 0.85x1.7 smd: 1(0.9,0) 2(-0.9,0)
L2520
  rect 0.85x2 smd: 1(-1.15,0) 2(1.15,0)
MHOLE_3D0X2D0
  oval 4.2x3.2 hole 3x2 rot 45: 1(0,0)
MICROUSB_B_NJ5P
  rect 0.4x1.35 smd: 1(1.3,0) 2(0.65,0) 3(0,0) 4(-0.65,0) 5(-1.3,0)
  rect 1.4x2 hole 0.5x1.2: 6(3.625,2.625) 7(-3.625,2.625)
  oval 1.1x1.35 hole 0.6: 8(-2.425,-0.125) 9(2.425,-0.125)
  rect 1.2x1.5 smd: 10(-0.8,2.625) 11(0.8,2.625)
MSOP8_0D65
  oval 0.35x1.5 smd: 1(-0.975,-2.3) 2(-0.325,-2.3) 3(0.325,-2.3) 4(0.975,-2.3) 5(0.975,2.3) 6(0.325,2.3) 7(-0.325,2.3) 8(-0.975,2.3)
QFN32_0D5_SZ18201
  rect 0.7x0.25 smd: 1(-2.45,1.75) 2(-2.45,1.25) 3(-2.45,0.75) 4(-2.45,0.25) 5(-2.45,-0.25) 6(-2.45,-0.75) 7(-2.45,-1.25) 8(-2.45,-1.75) 17(2.45,-1.75) 18(2.45,-1.25) 19(2.45,-0.75) 20(2.45,-0.25) 21(2.45,0.25) 22(2.45,0.75) 23(2.45,1.25) 24(2.45,1.75)
  rect 0.25x0.7 smd: 9(-1.75,-2.45) 10(-1.25,-2.45) 11(-0.75,-2.45) 12(-0.25,-2.45) 13(0.25,-2.45) 14(0.75,-2.45) 15(1.25,-2.45) 16(1.75,-2.45) 25(1.75,2.45) 26(1.25,2.45) 27(0.75,2.45) 28(0.25,2.45) 29(-0.25,2.45) 30(-0.75,2.45) 31(-1.25,2.45) 32(-1.75,2.45)
  custom 0.85x0.85 smd: 33(0,0)
QFP16_1D27
  rect 1.4x0.5 smd: 1(-4.6,4.445) 2(-4.6,3.175) 3(-4.6,1.905) 4(-4.6,0.635) 5(-4.6,-0.635) 6(-4.6,-1.905) 7(-4.6,-3.175) 8(-4.6,-4.445) 9(4.6,-4.445) 10(4.6,-3.175) 11(4.6,-1.905) 12(4.6,-0.635) 13(4.6,0.635) 14(4.6,1.905) 15(4.6,3.175) 16(4.6,4.445)
R0402
  rect 0.45x0.55 smd: 1(-0.52,0) 2(0.52,0)
R0603
  rect 0.76x0.76 smd: 1(-0.762,0) 2(0.762,0)
SMB
  rect 2x2.8 smd: 1(2.5,0) 2(-2.5,0)
SOD323
  rect 0.9x0.9 smd: 1(-1.05,0) 2(1.05,0)
SOT23
  rect 0.8x1.1 smd: 1(-0.95,-1.35) 2(0.95,-1.35) 3(0,1.35)
SOT23-5
  rect 0.6x1.5 smd: 1(-0.95,-1.5) 2(0,-1.5) 3(0.95,-1.5) 4(0.95,1.5) 5(-0.95,1.5)
SOT23-6
  rect 1x0.4 smd: 1(-1.4,0.95) 2(-1.4,0) 3(-1.4,-0.95) 4(1.4,-0.95) 5(1.4,0) 6(1.4,0.95)
SW2_SMD
  rect 2.5x1.5 smd: 1(-3.5,0) 2(3.5,0)
TEST_SMD
  round 1 smd: 1(0,0)
TFCARD
  round 1 hole 1 unplated: (-4.95,-10.6) (3.05,-10.6)
  rect 0.7x1.8 smd: 1(2.25,0.2) 2(1.15,0.2) 3(0.05,0.2) 4(-1.05,0.2) 5(-2.15,0.2) 6(-3.25,0.2) 7(-4.35,0.2) 8(-5.45,0.2) 9(-6.55,0.2)
  rect 1.6x1.4 smd: 10(-8,-0.6) 13(6.85,-0.6)
  rect 1.2x2.2 smd: 11(-7.75,-10.2) 12(7.75,-10.2)
WSOP8_1D27
  rect 1.9x0.5 smd: 1(-3.645,1.905) 2(-3.645,0.635) 3(-3.645,-0.635) 4(-3.645,-1.905) 5(3.645,-1.905) 6(3.645,-0.635) 7(3.645,0.635) 8(3.645,1.905)

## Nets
AVDD33: C127.1 C128.1 FB2.1 U8.7(AVDD33_1)
AVDDL_REG: C59.1 C60.1 U6.R16(AVDDL_REG)
DVDD1V2OUT: C57.1 C58.1 U6.T14(DVDD1V2OUT)
GND: C1.2 C2.2 C3.2 C5.2 C7.2 C8.2 C11.2 C12.2 C13.2 C14.2 C15.2 C17.2 C18.2 C19.2 C20.2 C21.2 C22.2 C24.2 C25.2 C26.2 C27.2 C28.2 C29.2 C30.2 C31.2 C32.2 C33.2 C34.2 C35.2 C36.2 C37.2 C38.2 C39.2 C41.2 C42.1 C43.2 C44.2 C45.2 C46.2 C47.2 C48.2 C49.2 C50.2 C51.2 C52.2 C53.2 C54.2 C55.2 C57.2 C58.2 C59.2 C60.2 C61.1 C62.2 C63.2 C64.2 C65.2 C66.2 C69.2 C70.2 C71.2 C72.2 C73.2 C74.2 C75.2 C76.2 C78.2 C79.2 C80.1 C81.1 C82.1 C83.2 C84.2 C85.2 C86.2 C87.2 C88.2 C89.2 C90.2 C91.2 C93.2 C94.2 C95.2 C96.1 C97.1 C98.1 C99.2 C100.2 C101.2 C102.2 C103.2 C104.2 C106.2 C108.2 C110.2 C111.2 C112.2 C113.2 C114.2 C119.2 C125.2 C126.1 C127.2 C128.2 D1.1 D3.1(ANODE) D4.2 D5.1(ANODE) D6.1(ANODE) H1.1(A) H2.1(A) H3.1(A) H4.1(A) J1.3 J1.5(S1) J1.6(S2) J2.6(VSS2) J2.10(GND_2) J2.11(GND_1) J2.12(PAD1) J2.13(PAD2) J3.7 J3.10 J3.15 J3.20 J3.27 J3.29 J3.37(S1) J3.38(S2) J4.5(GND1) J4.6(GND2) J4.7(GND3) J4.8(GND4) J4.9(GND5) J4.10(GND6) J4.11(GND7) J5.7 J5.9(S1) J5.10(S2) J6.3(S1) J6.4(S2) J7.3(S1) J7.4(S2) J8.2 J8.5(S1) J8.6(S2) R3.1 R8.1 R9.1 R14.2 R16.2 R17.1 R18.2 R21.1 R26.2 R27.1 R41.2 R46.1 R47.1 R49.1 R50.2 R59.1 R64.2 R71.1 R78.1 R88.1 R89.1 R92.1 R98.1 SW1.1 SW2.1 U1.2(GND) U2.2(GND) U3.2(GND) U4.2(GND) U5.2(GND) U6.C9(DDRPLL_VSSA) U6.G5(PLL_AVSS) U6.G6(VSS1) U6.G7(VSS2) U6.G8(VSS3) U6.G9(VSS4) U6.G10(VSS5) U6.G11(VSS6) U6.G12(VSS7) U6.G13(VSS8) U6.J6(VSS9) U6.J7(VSS10) U6.J8(VSS11) U6.J9(VSS12) U6.J10(VSS13) U6.J11(VSS14) U6.J12(VSS15) U6.K6(VSS16) U6.K7(VSS17) U6.K8(VSS18) U6.K9(VSS19) U6.K10(VSS20) U6.K11(VSS21) U6.K12(VSS22) U6.L6(VSS23) U6.L7(VSS24) U6.L8(VSS25) U6.L9(VSS26) U6.L10(VSS27) U6.L11(VSS28) U6.L12(VSS29) U6.M7(VSS30) U6.M8(VSS31) U6.M9(VSS32) U6.M10(VSS33) U6.M11(VSS34) U6.M12(VSS35) U6.M13(VSS36) U6.N5(CSI_VSSA) U6.N12(VSS37) U6.N13(SADC_AGND) U6.P4(CODEC_AVSS) U7.4(GND) U8.33(GND) U10.7(GND) Y1.2 Y1.4
VBUS: TP10.1 U6.U3(VBUS)
VCC_0V8: C21.1 C22.1 C23.2 C43.1 C44.1 C45.1 C46.1 C47.1 C48.1 C49.1 C50.1 C52.1 C53.1 C55.1 C113.1 FB4.1 FB8.2 L4.2 R63.2 TS1.1 U6.H5(VDD1) U6.H6(VDD2) U6.H7(VDD3) U6.H8(VDD4) U6.H9(VDD5) U6.H10(VDD6) U6.H11(VDD7) U6.H12(VDD8) U6.H13(VDD9) U6.J5(VDD10) U6.J13(VDD11) U6.K5(VDD12) U6.K13(VDD13) U6.L5(VDD14) U6.L15(VDD_RTC) U6.M5(VDD15) U6.M6(VDD16) U6.N6(VDD17) U6.N7(VDD18) U6.N8(VDD19) U6.N9(VDD20) U6.N10(VDD21)
VCC_1V8: C16.1 C17.1 C31.1 C38.1 C76.1 C83.1 C87.1 C88.1 C114.1 FB1.2 FB3.2 FB5.1 FB7.1 FB9.2 L5.2 R20.1 R62.1 R86.2 TP5.1 U6.C4(VDDIO2) U6.K2(VDDIO18_2) U6.L17(VDDIO_RTC) U6.N11(VDDIO18_1) U6.N16(SADC_VREFP) U6.N17(SADC_AVDD)
VCC_3V3: C4.1 C5.1 C39.1 C51.1 C81.2 C89.1 C90.1 C91.1 C92.1 C99.1 C100.1 D2.1(ANODE) FB2.2 FB6.1 J3.1 J3.2 J8.1 L1.2 Q1.2(SOURCE) R2.2 R22.2 R34.1 R37.1 R44.1 R55.2 R56.2 R57.1 R58.1 R65.2 R68.2 R69.2 R70.2 R87.1 R94.2 TP1.1 U6.J14(VDDIO33_2) U6.P9(VDDIO33_1) U7.8(VCC) U8.14(DVDD33_1)
VCC_5V: C2.1 C10.1 C11.1 C12.1 C13.1 C18.1 C19.1 C20.1 C108.1 J3.34 J3.35 J3.36 L2.2 R1.1 R5.1 R6.1 R10.1 R11.1 R85.2 TP4.1 U1.4(IN) U3.4(IN) U4.4(IN) U5.4(IN) U10.6(VDD)
VCC_12V: C1.1 C7.1 C8.1 D1.2 J1.4 R4.1 TP2.1 U2.5(VIN)
VCC_DDR: C9.1 C15.1 C24.1 C25.1 C26.1 C27.1 C28.1 C32.1 C33.1 C34.1 C35.1 C37.1 C40.2 C41.1 L3.2 R7.2 R15.2 TP3.1 U6.E6(VDDMEM1) U6.E7(VDDMEM2) U6.E8(VDDMEM3) U6.E9(VDDMEM4) U6.E10(VDDMEM5) U6.E11(VDDMEM6) U6.E12(VDDMEM7) U6.F5(DDRVDD1) U6.F6(DDRVDD2) U6.F7(DDRVDD3) U6.F8(DDRVDD4) U6.F9(DDRVDD5) U6.F10(DDRVDD6) U6.F11(DDRVDD7) U6.F12(DDRVDD8)
VDDMSC0: C93.1 C94.1 J2.4(VDD) Q1.3(DRAIN) R29.1 R30.1 R31.1 R32.1 R33.1
ACTA: J5.6 R74.2 R77.1
BOOTSEL0: R55.1 SW1.2 U6.A9(BOOT_SEL0_PC00)
BOOTSEL1: R56.1 R59.2 U6.B9(BOOT_SEL1_PC01)
CIM_MCLK: J3.28 R67.1
CLK_CTL: R92.2 U8.12(RXD[3]/CLK_CTL)
CORE_FB: C23.1 R63.1 R64.1 U5.5(FB)
CSI_VCC08: C84.1 C85.1 FB8.1 U6.N2(CSI_VCCA08)
CSI_VCC18: C29.1 C86.1 FB9.1 U6.K3(CSI_VCCA18)
DDR_VREF: C40.1 C42.2 R15.1 R17.2 U6.E5(DDR_VREF)
DDRPLL: C54.1 C64.1 FB1.1 U6.B8(DDRPLL_VCCA)
DVP_D0: J3.11 U6.L2(CSI_DATAN0_DVP_D0)
DVP_D1: J3.12 U6.L1(CSI_DATAP0_DVP_D1)
DVP_D2: J3.13 U6.N1(CSI_DATAN1_DVP_D2)
DVP_D3: J3.14 U6.M3(CSI_DATAP1_DVP_D3)
DVP_D4: J3.16 U6.M2(CSI_CLKN_DVP_D4)
DVP_D5: J3.17 U6.L3(CSI_CLKP_DVP_D5)
DVP_D6: J3.18 U6.H2(SD0_DVP_D6_PA06)
DVP_D7: J3.19 U6.H3(SD1_DVP_D7_PA07)
DVP_D8: J3.21 U6.G1(SD2_DVP_D8_PA08)
DVP_D9: J3.22 U6.G2(SD3_DVP_D9_PA09)
DVP_D10: J3.23 U6.G3(SD4_DVP_D10_PA10)
DVP_D11: J3.24 U6.F2(SD5_DVP_D11_PA11)
DVP_HSYNC: J3.8 U6.J2(CS2_DVP_HSYNC_PA16)
DVP_PCLK: J3.26 U6.F3(SA0_DVP_PCLK__PA14)
DVP_PWDN: J3.30 U6.E2(WAIT_PA19)
DVP_RST: J3.33 U6.E3(SA2_PA18)
DVP_VSYNC: J3.9 U6.J3(RD_DVP_VSYNC_PA17)
EN_DLDO: R27.2 R69.1 U6.U15(EN_DLDO)
EXCLKI: C80.2 R23.2 U6.C1(EXCLK_XIN) Y1.1
EXCLKO: R23.1 R24.2 U6.D2(EXCLK_XOUT)
GMAC_MDCK: U6.R10(GMAC_MDCK_SMB2_SDA_PB10) U8.22(MDC)
GMAC_MDIO: R37.2 U6.T10(GMAC_MDIO_SMB2_SCK_PB11) U8.23(MDIO)
GMAC_PHY_CLK: R66.1 U8.31(XTAL_IN)
GMAC_RST_N: C125.1 R70.1 R99.2 U6.A11(DMIC_CLK_SMB2_SCK_PB28) U8.21(RESET_N)
GMAC_RXD0: U6.U13(GMAC_RXD0_PWM6_PB15) U8.9(RXD[0])
GMAC_RXD1: R44.2 U6.R12(GMAC_RXD1_PWM7_PB16) U8.10(RXD[1])
GMAC_RXDV: U6.U9(GMAC_RXDV_PWM3_PB09) U8.26(CRS/CRS_DV)
GMAC_TXCLK: R19.1 U6.T12(GMAC_TXCLK_PB06)
GMAC_TXD0: U6.R11(GMAC_TXD0_PWM4_PB13) U8.16(TXD[0])
GMAC_TXD1: U6.T11(GMAC_TXD1_PWM5_PB14) U8.17(TXD[1])
GMAC_TXEN: U6.U11(GMAC_TXEN_PWM2_PB08) U8.20(TXEN)
HPOUTL: C107.2 U6.T1(HPOUTL)
I2C0_SCK: J3.3 U6.J4(SD7_SMB0_SCK_PA13)
I2C0_SDA: J3.6 U6.J1(SD6_SMB0_SDA_PA12)
IR: J3.25 U6.B12(DMIC_DAT0_UART4_TXD_PB29)
IRCUTN: J3.31 U6.E17(MSC1_D1_PB18)
IRCUTP: J3.32 U6.E16(MSC1_D0_PB17)
LINKA: J5.8 R75.2 R76.1
MCLK: R67.2 U6.E1(SA1_DVP_MCLK_PA15)
MDI_RN: R40.2 R73.2 U9.1(TD+/RD+)
MDI_RP: R39.2 R72.2 U9.3(TD-/RD-)
MDI_TN: R28.2 R36.2 U9.6(RD+/TD+)
MDI_TP: R13.2 R35.2 U9.8(RD-/TD-)
MICBIAS: C78.1 C79.1 C110.1 R81.1 U6.P3(MICBIAS)
MICNL: C68.2 C105.1 J6.1 R48.1
MICPL: C67.2 C105.2 J6.2 R51.2
MSC0_CLK_PB04: J2.5(CLK) R25.1
MSC0_CMD_PB05: J2.3(CMD) R30.2 U6.G17(MSC0_CMD_PB05)
MSC0_D0_PB00: J2.7(DAT0) R29.2 U6.H16(MSC0_D0_PB00)
MSC0_D1_PB01: J2.8(DAT1) R31.2 U6.J15(MSC0_D1_PB01)
MSC0_D2_PB02: J2.1(DAT2) R32.2 U6.G15(MSC0_D2_PB02)
MSC0_D3_PB03: J2.2(DAT3) R33.2 U6.G16(MSC0_D3_PB03)
PHY_LED0: R74.1 U6.R13(LED0)
PHY_LED1: R75.1 U6.R15(LED1)
PHY_RST_N: C61.2 R99.1 U6.T13(PHY_RST)
PHYLED0: R77.2 R88.2 U8.24(LED0/PHYAD[0])
PHYLED1: R76.2 R89.2 U8.25(LED1/PHYAD[1])
PLL_AVDD: C30.1 C63.1 FB3.1 U6.D3(PLL_AVDD)
POR_CTRL: R20.2 R78.2 U6.K16(POR_CTL)
PPRST_: C111.1 R62.2 SW2.2 U6.L16(PPRST_)
RD_N: R73.1 U6.U17(RD_N)
RD_P: R72.1 U6.T17(RD_P)
RST_OUT: TP8.1 U6.J16(RST_OUT)
RX+: J5.3 U9.14(TX-/RX-)
RX-: J5.4 U9.16(TX+/RX+)
RX_DV: R68.1 U6.P14(RX_DV)
RXD3: R65.1 R71.2 U6.R14(RXD3)
RXDV: R87.2 U8.8(RXDV)
SD0_CD_N: C92.2 J2.9(CD) Q1.1(GATE) R34.2 U6.B11(DRV_VBUS_SMB2_SDA_PB27)
SFC_CS_N: R22.1 U6.T4(SFC0_CE_PA28) U7.1(C\S\)
SFC_SCLK: U6.R6(SFC0_CLK_PA27) U7.6(SCLK)
SFC_SIO0: U6.U5(SFC0_DT_IO0_PA23) U7.5(SI/SIO0)
SFC_SIO1: U6.R5(SFC0_DR_IO1_PA24) U7.2(SO/SIO1)
SFC_SIO2: U6.T5(SFC0_WP_IO2_PA26) U7.3(W\P\/SIO2)
SFC_SIO3: U6.T6(SFC0_HOLD_IO3_PA25) U7.7(R\E\S\E\T\/SIO3)
SPEAK_EN: R50.1 U6.B10(GPIO_PB31) U10.1(/SD)
TD_N: R28.1 U6.U16(TD_N)
TD_P: R13.1 U6.T16(TD_P)
TRXN0: R36.1 U8.4(TRXN0)
TRXN1: R40.1 U8.6(TRXN1)
TRXP0: R35.1 U8.3(TRXP0)
TRXP1: R39.1 U8.5(TRXP1)
TX+: J5.1 U9.9(RX-/TX-)
TX-: J5.2 U9.11(RX+/TX+)
UART1_RX: R61.2 U6.F16(UART1_RXD_PB24)
UART1_RXD: J8.3 R57.2 R61.1
UART1_TX: R60.2 U6.F15(UART1_TXD_PB23)
UART1_TXD: J8.4 R58.2 R60.1
USB0PN: D5.2(CATHODE) J4.2(D-) R100.2
USB0PP: D3.2(CATHODE) J4.3(D+) R101.2
USB_AVD08: C71.1 C72.1 FB4.2 U6.R4(USB_AVD08)
USB_AVD18: C36.1 C73.1 FB5.2 U6.T3(USB_AVD18)
USB_AVD33: C74.1 C75.1 FB6.2 U6.R3(USB_AVD33)
USBID: TP7.1 U6.U2(USB0ID)
N16515966: C10.2 R6.2 R8.2 U2.3(FB)
N16516036: R4.2 U2.4(EN)
N16516040: C6.1 U2.1(BS)
N16516056: C6.2 L2.1 U2.6(LX)
N16516370: C3.1 R1.2 U1.1(EN)
N16516568: C4.2 R2.1 R3.2 U1.5(FB)
N16516600: L1.1 U1.3(LX)
N16516732: D2.2(CATHODE) R14.1
N16520392: C95.1 C119.1 D6.2(CATHODE) J4.1(VBUS) R85.1
N16524050: J7.2 U10.5(VO+)
N16524058: J7.1 U10.8(VO-)
N16524110: R53.1 U10.4(-IN)
N16524120: C107.1 R53.2
N16524124: C106.1 R52.2
N16524196: R52.1 U10.3(+IN)
N16524342: C56.2 R51.1 R81.2
N16524476: C56.1 R48.2 R49.2
N16557488: C82.2 R24.1 Y1.3
N16609473: R16.1 U6.F13(DDR_ZQ)
N16609477: R18.1 U6.D9(RZQ)
N16629326: R46.2 U8.28(RXER)
N16629374: R47.2 U8.32(XTAL_OUT)
N16629796: R41.1 U8.1(PBIAS)
N16629982: C103.1 C104.1 U8.29(DVDDL_REG)
N16630018: C101.1 C102.1 U8.2(AVDDL_REG)
N16630046: R94.1 U8.30(NC)
N16630124: C98.2 U9.7(CT2)
N16630144: D4.1 R93.2 U9.10(CT3) U9.13(MCT) U9.15(CT4)
N16630182: C97.2 U9.5(CT)
N16630194: C96.2 U9.2(CT1)
N16630328: C126.2 R93.1
N16679971: R21.2 U6.D4(EFUSE_AVDD)
N16680187: C65.1 C66.1 FB7.2 U6.R1(CODEC_AVDD)
N16680357: C69.1 C70.1 U6.R2(VCM)
N16685513: R66.2 U6.T9(GMAC_PHY_CLK_PB07)
N16707574: R101.1 U6.T2(USB0PP)
N16707578: R100.1 U6.U1(USB0PN)
N16707590: C68.1 U6.P2(MICNL)
N16707598: TP9.1 U6.P15(SADC_VIN0)
N16710875: R25.2 U6.H15(MSC0_CLK_PB04)
N16712105: C67.1 U6.N3(MICPL)
N16792128: R26.1 U6.T15(RBIAS)
N16932770: C62.1 R11.2 U4.1(EN)
N16932828: L5.1 U4.3(LX)
N16932830: C16.2 R86.1 R98.2 U4.5(FB)
N16959210: C14.1 R5.2 U3.1(EN)
N16959271: C9.2 R7.1 R9.2 U3.5(FB)
N16959277: L3.1 U3.3(LX)
N16959996: C112.1 R10.2 U5.1(EN)
N16960077: L4.1 U5.3(LX)
N16967238: R19.2 U8.15(TXC)

Pads without a net: J1 1 2; J3 4 5; J4 4; J5 5; U6 A1 A2 A3 A5 A7 A13 A15 A16 A17 B1 B2 B3 B4 B5 B6 B7 B13 B14 B15 B16 B17 C2 C3 C5 C6 C7 C8 C10 C11 C12 C13 C14 C15 C16 C17 D14 D15 D16 E15 J17 K15 L13 M15 M16 N15 P16 R7 R8 R9 R17 T7 T8 U7; U8 11 13 18 19 27; U9 4 12; U10 2

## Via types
v1: diameter 0.406, hole 0.203, TOP to BOTTOM, 497 vias

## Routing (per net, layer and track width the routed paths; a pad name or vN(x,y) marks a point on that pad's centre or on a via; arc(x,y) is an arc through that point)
AVDD33: length 3.8
  TOP w0.254: U8.7 v1(17.58,14.78)
  BOTTOM w0.254: FB2.1 18.92,15.86 C127.1 18.4,15.77 C128.1 17.58,15.74 v1(17.58,14.78)
AVDDL_REG: length 2.1
  TOP w0.254: U6.R16 v1(27.48,19.29)
  BOTTOM w0.305: C60.1 C59.1 27.52,19.25 v1(27.48,19.29)
DVDD1V2OUT: length 2.8
  TOP w0.254: v1(25.71,20.73) 25.89,20.9 27,20.9 27,20.91 U6.T14
  BOTTOM w0.305: C57.1 C58.1 v1(25.71,20.73)
GND: length 206.6
  TOP w0.102: v1(30.72,22.53) U6.K12 U6.J12
  TOP w0.127: U6.G6 v1(33.32,25.78) U6.G7 ; U6.K11 v1(30.72,22.53) ; U6.L11 v1(30.07,22.53) ; U6.K10 v1(30.72,23.18) ; U6.N13 v1(28.77,21.23) ; 35.12,31.83 35.12,29.67 34.95,29.49 34.95,29.21 ; U6.M11 v1(29.42,22.53) ; U6.G13 v1(33.32,21.88) U6.G12 ; U6.G5 v1(33.32,27.08) ; U6.G10 v1(33.32,23.18) U6.G11 ; U6.L12 v1(30.07,21.88) ; U6.G9 v1(33.32,24.48) U6.G8 ; v1(15.54,25.78) 15.69,25.93 ; U6.M12 v1(29.42,21.88)
  TOP w0.203: v1(40.76,25.83) 41.09,25.5 SW2.1 ; 26.06,24.77 25.83,24.99 22.83,24.99 22.12,24.28 17.19,24.28 16.43,25.04 15.98,25.04 15.54,25.49 v1(15.54,25.78) 15.08,25.78 14.17,24.87 v1(14.02,24.87) 12.73,24.87 12.47,25.13 12.47,25.47 14.23,27.23 15.06,27.23 ; J2.10 22.37,14.27 23.47,15.37 25.06,15.37 27.58,17.89 27.58,17.98 v1(28.23,18.64) ; C108.2 14.5,31.27 ; C108.2 v1(13.56,31.27) ; C108.2 14.08,31.46 13.79,31.75 v1(13.61,31.75) ; v1(22.46,29.12) 22.07,28.73 21.08,28.73 19.91,27.56 ; R92.1 21.56,17.68 21.61,17.63 v1(21.66,17.63) ; R21.1 38.82,28.35 v1(38.82,28.35) ; v1(28.27,30.51) 28.19,30.51 27.28,31.42 24.56,31.42 24.23,31.75 23.41,31.75 ; R26.2 23.63,18.14 23.63,17.56 v1(23.62,17.55) 23.01,16.94 22.83,16.94 21.54,15.65 19.73,15.65 v1(19.25,15.16) ; 15.69,25.93 15.97,26.21 16.91,26.21 17.19,26.49 18.06,26.49 18.08,26.47 19.75,26.47 19.87,26.34 v1(20.85,26.34) 21,26.19 21.49,26.19 23.14,27.84 23.14,28.27 v1(23.16,28.3) ; 17.06,30.33 19.83,30.33 20.02,30.52 R49.1 ; 15.87,33 v1(15.83,33) ; v1(34.25,34.58) 34.11,34.58 33.74,34.22 33.74,33.35 C82.1 35,32.87 Y1.4 35.25,32.5 35.12,32.37 35.12,31.83
  TOP w0.254: U6.C9 v1(35.92,24.48) ; 19.91,27.56 19.83,27.48 18.36,27.48 18.35,27.49 15.31,27.49 15.06,27.23 ; v1(20.98,30.48) 20.9,30.48 20.24,31.14 R49.1 ; U6.M8 U6.L8 ; v1(28.72,21.87) 29.06,22.21 U6.N12 ; C100.2 21.26,19.72 C99.2 21.12,19.75 ; v1(37.79,30.76) 38.55,31.52 38.55,33.25 38.24,33.57 C80.1 37.7,33.57 Y1.2 v1(36.92,34.99) 36.6,35.31 v1(36.04,35.31) 34.97,35.31 v1(34.25,34.58) ; U6.P4 v1(28.14,27.71) ; v1(30.07,21.88) U6.M13
  TOP w0.305: v1(10.61,17.14) 10.78,17.14 C103.2 11.24,16.79 C104.2 ; U6.J8 31.37,24.48 v1(31.37,24.48) ; U10.7 13.67,28.66 13.69,28.68 v1(13.71,28.68) 14.08,29.04 C108.2 ; U6.J10 v1(31.37,23.18) U6.J11 ; v1(30.72,25.13) U6.L7 U6.M7 ; v1(30.72,25.13) U6.K8 31.05,24.81 v1(31.37,24.48) ; v1(30.72,25.13) U6.L8 ; v1(30.72,25.13) U6.K7 ; R78.1 v1(31.19,16.69) ; U6.J6 31.69,26.11 v1(31.37,25.78) ; v1(31.37,24.48) 31.7,24.16 U6.J9 ; v1(31.37,24.48) 31.37,24.48 U6.K9 ; R47.1 R41.2 v1(10.61,14.05) ; v1(24.58,20.09) 24.58,19.85 C61.1 ; R59.1 v1(39.21,25.17) ; v1(30.07,23.83) 29.75,24.16 U6.M9 ; v1(30.07,23.83) 30.4,24.15 U6.L9 v1(30.72,23.83) ; v1(30.07,23.83) 29.75,23.51 U6.M10 ; C104.2 10.71,17.7 ; C104.2 R46.1 ; v1(13.86,22.17) 13.86,22.25 13.92,22.3 R89.1 ; U6.K7 v1(31.37,25.78) ; U6.K7 v1(30.72,25.78) U6.L6 ; v1(31.37,25.78) U6.J7 ; v1(31.37,25.78) U6.K6 ; v1(39.29,24.03) 39.16,23.9 R18.2 ; v1(30.72,24.48) U6.K9 ; U6.K9 v1(30.72,23.83) ; U6.N12 v1(29.42,22.53) ; v1(30.72,23.83) U6.L10 ; v1(20.04,28.4) 20.15,28.51 C106.2 ; U6.N5 v1(28.77,27.08)
  TOP w0.406: v1(27.1,15.34) 27.1,15.34 27.12,15.32 J2.6
  TOP w0.508: 9.84,26.11 J4.8 ; J4.8 10.82,26.96 ; J4.8 8.86,26.96 ; 8.86,22.11 J4.9 ; J4.9 9.84,21.26 ; J4.9 10.82,22.11 ; J4.9 9.84,22.97
  L2_GND w0.508: 8.86,22.11 J4.9 ; J4.9 9.84,21.26 ; J4.9 9.84,22.97 ; J4.9 10.82,22.11 ; J4.8 10.82,26.96 ; J4.8 9.84,26.11 ; J4.8 9.84,27.82 ; J4.8 8.86,26.96
  L3_PWR w0.508: 8.86,26.96 J4.8 ; J4.8 9.84,26.11 ; J4.8 10.82,26.96 ; J4.8 9.84,27.82 ; 8.86,22.11 J4.9 ; J4.9 9.84,22.97 ; J4.9 9.84,21.26 ; J4.9 10.82,22.11
  BOTTOM w0.203: C86.2 33.59,29.59 33.95,29.59 C30.2 ; J3.37 10.98,35.72 11.76,36.5 v1(11.76,36.58) ; 20.02,18.38 C112.2 ; R71.1 21.68,17.7 21.68,17.64 v1(21.66,17.63) 21.66,17.5 22.06,17.11 R27.1 ; C66.2 22.32,30.37 v1(22.32,30.2) ; v1(10.61,14.05) 10.5,13.94 J8.2
  BOTTOM w0.254: 31.57,9.81 v1(31.57,9.47) v1(31.57,7.44) v1(31.57,6.55) 31.57,5.69 v1(31.62,5.64) ; R8.1 31.57,9.8 ; C11.2 33.85,7.01 v1(33.52,7.34) ; C17.2 25.35,8.33 v1(25.65,8.03) ; C70.2 25.37,29.36 25.34,29.39 v1(25.09,29.39) ; C12.2 v1(32.84,7.21) ; C88.2 v1(37.14,26.05)
  BOTTOM w0.305: U5.2 20.98,21.03 21.28,20.73 v1(21.28,20.6) ; v1(27.47,24.48) 27.38,24.39 C39.2 C89.2 v1(26.49,24.64) ; C41.2 v1(37.79,30.76) ; C27.2 36.41,24.97 v1(35.92,24.48) ; C24.2 36.24,23.18 v1(35.92,23.18) ; C24.2 36.79,22.63 C25.2 36.89,21.92 C33.2 ; C24.2 C26.2 ; v1(26.31,2.87) 26.74,3.3 C18.2 ; v1(27.75,12.4) 27.21,11.86 24.91,11.86 v1(23.9,10.85) v1(23.9,9.47) v1(23.9,8) v1(23.9,6.27) 23.9,5.28 24.2,4.98 R98.1 v1(24.44,4.37) ; C62.2 v1(29.59,8.26) ; C59.2 C60.2 ; v1(40.13,11.38) 39.82,11.07 C7.2 C8.2 ; C3.2 v1(23.24,8.26) ; C5.2 19.3,8.32 v1(19.3,8.03) ; C54.2 v1(39.29,24.03) ; U4.2 v1(27.5,7.14) ; v1(34.84,17.53) 34.89,17.53 34.9,17.51 C15.2 ; C76.2 C38.2 v1(27.81,17.04) ; C69.2 C70.2 ; C64.2 39.01,24.92 39.21,25.12 v1(39.21,25.17) ; v1(20.85,26.34) 21.03,26.16 22.25,26.16 22.55,26.47 C36.2 C73.2 ; v1(10.74,25.6) 10.51,25.84 J4.5 ; v1(37.14,26.05) 37.01,26.19 C28.2 ; C43.2 27.51,27.11 v1(27.47,27.08) 26.97,27.08 26.57,26.68 C72.2 C71.2 ; C42.1 38.43,27.97 v1(38.82,28.35) ; U1.2 v1(21.15,7.11) ; R9.1 v1(33.8,13.97) ; U2.2 v1(35.2,8.79) ; R17.1 v1(38.88,28.85)
  BOTTOM w0.406: C98.1 v1(11.25,8.94) ; C97.1 v1(14.93,7.32) ; C20.2 15.32,22 C19.2 14.92,22.23 14.82,22.33 14.82,22.91 ; C96.1 v1(16.33,7.14) ; C14.2 v1(39.52,17.37)
  BOTTOM w0.508: 8.86,22.11 J4.9 ; J4.9 9.84,21.26 ; J4.9 10.82,22.11 ; 9.84,26.11 J4.8 ; J4.8 9.84,27.82 ; J4.8 10.82,26.96 ; J4.8 8.86,26.96
  vias: v1(5.71,34.54) v1(5.71,31.27) v1(5.74,22.1) v1(5.66,19.13) v1(5.71,16.18) v1(5.69,13.92) v1(5.69,12.37) v1(5.71,10.16) v1(5.74,8.89) v1(5.71,7.59) v1(5.71,5.89) v1(5.69,3.86) v1(5.76,29.36) v1(5.79,27.1) v1(5.81,24.54) v1(6.65,27.05) v1(6.7,15.47) v1(6.93,6.55) v1(7.46,21.87) v1(7.59,29.41) v1(7.77,31.14) v1(7.92,17.27) v1(7.95,6.91) v1(8.3,33.71) v1(8.28,24.51) v1(8.33,23.24) v1(8.45,30.43) v1(8.63,26.04) v1(8.66,37.29) v1(8.91,3.91) v1(8.89,0.66) v1(9.34,34.82) v1(9.29,10.97) v1(9.5,3.07) v1(9.57,30.71) v1(9.6,1.93) v1(10.16,8.64) v1(10.31,10.64) v1(10.38,21.13) v1(10.44,0.66) v1(10.61,4.27) v1(10.89,26.8) v1(11.02,24.87) v1(10.99,7.87) v1(11.22,12.09) v1(11.27,23.72) v1(11.63,13.36) v1(11.76,37.26) v1(12.19,9.07) v1(12.26,35.46) v1(12.52,22.56) v1(12.65,36.5) v1(13.18,23.8) v1(13.74,37.39) v1(13.71,9.17) v1(13.7,5.25) v1(13.86,8.18) v1(14.04,28.12) v1(14.02,6.25) v1(14.3,10.74) v1(14.65,34.8) v1(14.7,23.14) v1(14.98,5.31) v1(15.06,19.2) v1(15.06,17.93) v1(15.06,16.66) v1(15.41,11.73) v1(15.85,31.6) v1(15.92,35.69) v1(15.97,12.5) v1(16.07,37.36) v1(16.13,6.32) v1(16.33,19.2) v1(16.33,17.93) v1(16.33,16.66) v1(16.58,9.47) v1(16.84,12.37) v1(16.79,5.61) v1(16.86,10.87) v1(17.01,4.29) v1(17.37,9.45) v1(17.47,24.79) v1(17.52,8.15) v1(17.47,5.71) v1(17.6,19.2) v1(17.62,17.93) v1(17.6,16.66) v1(17.78,34.85) v1(17.9,11.63) v1(18.06,4.22) v1(18.46,14.3) v1(18.61,22.07) v1(18.55,20.43) v1(18.64,8.03) v1(18.64,7.42) v1(18.69,15.16) v1(18.87,4.24) v1(19.3,7.42) v1(19.53,19.1) v1(19.6,4.01) v1(19.76,37.36) v1(19.95,6.31) v1(19.96,3.12) v1(20.6,11.89) v1(20.77,37.36) v1(20.82,9.09) v1(20.82,0.64) v1(21.08,3.91) v1(21.05,2.82) v1(21.22,6.11) v1(21.36,9.09) v1(21.71,32.92) v1(21.69,31.62) v1(21.87,12.24) v1(22.3,35.66) v1(22.75,37.39) v1(23.41,11.96) v1(23.36,0.64) v1(24,3.48) v1(24.51,2.82) v1(24.76,37.39) v1(24.96,30.35) v1(24.96,8.03) v1(24.96,7.42) v1(25.6,4.22) v1(25.65,7.42) v1(25.93,30.3) v1(25.9,0.64) v1(26.03,17.7) v1(26.23,37.36) v1(26.29,31.75) v1(26.33,6.25) v1(26.31,3.81) v1(27.15,9.07) v1(27.22,37.36) v1(27.43,3.91) v1(27.4,2.82) v1(27.57,6.13) v1(27.68,9.07) v1(28.24,12.14) v1(28.27,0.64) v1(28.9,27.64) v1(28.86,16.46) v1(29.05,12.17) v1(30.63,0.64) v1(31.47,37.26) v1(31.49,34.75) v1(32.81,10.95) v1(32.89,37.34) v1(33.32,27.64) v1(33.4,2.13) v1(33.45,0.66) v1(33.69,9.01) v1(33.69,8.57) v1(33.8,15.32) v1(33.8,14.68) v1(33.8,13.34) v1(33.96,27.69) v1(34.34,10.36) v1(34.46,37.34) v1(34.57,7.14) v1(34.57,6.47) v1(34.84,16.74) v1(35.26,27.08) v1(35.33,10.97) v1(35.27,6.78) v1(35.28,3.1) v1(35.38,36.3) v1(35.53,9.75) v1(35.81,17.78) v1(35.86,16.31) v1(36.11,36.32) v1(36.16,7.8) v1(36.29,0.66) v1(36.42,37.34) v1(37.11,17.27) v1(37.23,14.3) v1(37.18,3.07) v1(37.28,15.14) v1(37.41,21.41) v1(37.51,20.7) v1(37.64,36.3) v1(37.77,16.1) v1(37.89,37.31) v1(37.97,34.42) v1(38.12,2.11) v1(38.53,35.41) v1(38.84,30.4) v1(38.81,15.16) v1(39.16,37.34) v1(39.19,22.58) v1(39.16,5.97) v1(39.21,4.11) v1(39.27,29.51) v1(39.26,0.69) v1(39.52,32.16) v1(39.62,20.9) v1(39.98,31.04) v1(39.98,17.83) v1(39.95,5.26) v1(40.13,12.12) v1(40.29,15.33) v1(40.43,10.13) v1(40.51,28.6) v1(40.89,10.95) v1(41.02,33.55) v1(41.15,21.05) v1(41.15,18.9) v1(41.54,32.77) v1(41.96,12.57) v1(42.06,10.95) v1(42.31,34.24) v1(42.3,32.95) v1(42.34,31.34) v1(42.34,28.93) v1(42.34,26.59) v1(42.26,13.41) v1(42.34,3.84) v1(42.37,24.1) v1(42.37,21.61) v1(42.36,18.97) v1(42.37,16.02)
VBUS: length 1.6
  TOP w0.254: U6.U3 26.15,27.71 25.22,27.71 TP10.1
VCC_0V8: length 19.1
  TOP w0.203: U6.H8 v1(32.67,24.48) U6.H9 ; U6.H7 v1(32.67,25.78) U6.H6 ; U6.H12 v1(32.67,21.88) ; U6.L5 v1(30.07,27.08) ; U6.N6 v1(28.77,26.43) ; U6.H11 v1(32.67,23.18) U6.H10 ; v1(32.02,27.08) U6.J5 ; U6.M5 v1(29.42,27.08) ; U6.H5 v1(32.67,27.08)
  TOP w0.254: U6.J13 v1(32.02,21.88) U6.H13 ; U6.N10 29.09,23.51 v1(28.77,23.83) 29.1,24.15 U6.N9 ; U6.M5 U6.M6 U6.N6 ; U6.N7 28.37,25.46 v1(28.37,25.45) ; v1(28.37,24.66) 28.51,24.81 U6.N8 ; U6.K5 v1(31.37,27.08) ; U6.L15 30.4,20.77 v1(30.78,21.16) ; U6.K13 v1(31.37,21.23)
  BOTTOM w0.102: C113.1 30.45,20.83 v1(30.78,21.16)
  BOTTOM w0.254: FB4.1 24.33,26.09
  BOTTOM w0.305: C22.1 22.31,24.92 22.31,25.16 21.99,25.48 ; 21.99,25.48 22.65,25.48 ; 21.99,25.48 20.91,25.48 19.68,24.24 C23.2 R63.2
  vias: v1(30.07,21.23)
VCC_1V8: length 87.9
  TOP w0.203: R62.1 38.73,16.92 38.21,17.44 ; R20.1 v1(30.3,16.46)
  TOP w0.254: v1(29.26,18.39) 29.1,18.55 U6.N17 U6.N16 ; v1(30.78,28.45) 30.79,28.45 U6.K2 ; U6.N11 v1(28.34,22.86) ; U6.L17 v1(30.11,18.67) ; v1(35.92,27.08) U6.C4
  TOP w0.635: v1(24.91,10.29) v1(25.7,10.29) 33.21,10.29 35.25,12.33 35.25,14.48 40.31,19.53 40.31,21.98 v1(39.82,22.46) v1(39.82,23.11)
  L3_PWR w0.254: v1(28.34,22.86) 28.14,22.65 28.14,20.91 ; 27.86,20.62 28.14,20.91 ; 28.14,20.91 28.42,20.62
  L3_PWR w0.305: v1(20.87,29.11) 20.87,29.01 20.77,28.91 20.77,27.58 26.78,21.58 26.78,21.02 27.17,20.62 28.42,20.62 28.87,20.18 28.87,18.78 v1(29.26,18.39)
  BOTTOM w0.254: v1(30.3,16.46) 30.3,17.79 C83.1 30.16,18.62 v1(30.11,18.67) ; 39.56,27.09 39.82,27.35 ; 39.56,27.09 C88.1 35.93,27.09 v1(35.92,27.08) ; 39.56,27.09 39.82,26.82 ; FB1.2 39.8,23.14 v1(39.82,23.11) ; C31.1 C114.1 28.34,22.59 v1(28.34,22.86) ; FB7.1 20.89,29.02 ; 20.89,29.02 20.77,28.91 20.77,27.33 21.45,26.65 FB5.1 ; 20.89,29.02 20.89,29.09 v1(20.87,29.11) ; 29.42,17.86 C76.1 ; FB9.2 33.39,30.36 32.84,30.91 32.05,30.91 31.34,30.2 31.34,29.82 30.97,29.45 C87.1 30.52,29.39 30.52,28.71 v1(30.78,28.45)
  BOTTOM w0.305: C17.1 24.93,9.71 24.44,9.23 C16.1 R86.2
  BOTTOM w0.406: FB9.2 33.55,30.25 34.06,30.76 FB3.2 35.44,32 38.07,32 39.82,30.25 v1(39.82,23.11) v1(39.82,22.46) ; v1(29.26,18.39) 29.42,18.23 C76.1 ; 29.42,17.86 C38.1 29.42,16.68 v1(29.64,16.46) v1(30.3,16.46)
VCC_3V3: length 113.8
  TOP w0.203: R70.2 v1(21.37,11.98) ; v1(10.54,16.46) 10.54,15.99 10.76,15.77 R94.2 ; R37.1 15.83,22.64 v1(16.33,23.14) ; v1(27.61,16.43) 28.23,16.43 28.52,16.72 R68.2 ; R56.2 v1(38.82,26.54) 38.82,26.72 R55.2
  TOP w0.254: U8.14 19.24,18.68 19.25,18.67 19.88,18.67 19.9,18.68 C100.1 20.71,18.68 v1(20.72,18.69) 20.76,18.66 C99.1 ; v1(21.18,16.38) 21.29,16.5 R44.1 ; U6.J14 31.77,20.83 31.8,20.83 31.85,20.78 33.04,20.78 v1(33.09,20.83) ; U6.P9 v1(28.12,23.83)
  L3_PWR w0.203: 16.53,15.65 16.52,15.63 v1(16.52,13.37)
  L3_PWR w0.254: 33.52,19.66 33.64,19.77 33.64,20.28 ; v1(21.81,29.18) 21.81,28.22 25.14,24.89 25.14,24.71 25.19,24.66 v1(25.19,24.56) ; v1(33.09,20.83) 33.64,20.28 ; 33.64,20.28 34.22,20.28 34.36,20.42 ; 33.64,20.28 33.93,19.99 ; 19.1,16.38 18.36,15.65 14.8,15.65 14.27,16.18 10.82,16.18 v1(10.54,16.46)
  L3_PWR w0.406: v1(16.33,23.14) 16.33,21.39 18.79,18.92 18.79,16.69 19.1,16.38 v1(21.18,16.38) ; 14.85,25.81 15.79,26.75 19.07,26.75 19.58,26.24 v1(19.58,26.06)
  L3_PWR w0.635: v1(13.2,35.59) 13.2,35.28 v1(13.46,35.03) 12.02,33.59 12.02,28.51 14.73,25.81 ; v1(16.33,23.14) 14.85,24.62 14.85,25.81
  BOTTOM w0.203: 20.21,13.13 v1(21.37,11.98) ; R58.1 10.88,16.8 v1(10.54,16.46) ; U7.8 19.57,26.12 19.58,26.11 v1(19.58,26.06) ; R57.1 11.59,12.75 J8.1 ; R87.1 v1(16.52,13.37)
  BOTTOM w0.254: v1(16.33,23.14) 15.38,24.09 R22.2 ; v1(33.09,20.83) 33.16,20.77 C51.1 C90.1 ; v1(21.81,29.18) 21.81,29.2 21.83,29.21 21.83,29.22 22.26,29.66 FB6.1 ; v1(25.19,24.56) 25.19,24.51 25.14,24.46 25.14,23.14 25.15,23.13 C89.1 C39.1 27.8,23.13 28.12,23.45 v1(28.12,23.83) ; C81.2 19.57,26.06 v1(19.58,26.06) ; v1(10.54,16.46) 9.27,16.46 8.96,16.15 8.96,13.11 9.32,12.75 J8.1 10.5,11.73 9.79,11.01 D2.1 ; v1(20.72,18.69) 21.18,18.24 v1(21.18,16.38) 21.15,16.41 FB2.2
  BOTTOM w0.305: 25.14,23.14 25.14,19.09 R65.2 R69.2 24.14,16.36 C92.1 ; 18.09,9.32 18.49,9.71 C5.1 ; 18.09,9.32 C4.1 R2.2 ; 18.09,9.32 18.09,9.94
  BOTTOM w0.406: v1(21.18,16.38) 21.23,16.33
  BOTTOM w0.635: 21.23,16.33 21.52,16.04 C91.1 R34.1 C92.1 24.88,16.04 Q1.2 26.99,16.52 v1(27.07,16.43) v1(27.61,16.43) ; J3.1 13.27,35.65 v1(13.2,35.59) 13.2,35.28 v1(13.46,35.03) 13.77,34.72 J3.2
  vias: v1(20.85,16.89)
VCC_5V: length 59.9
  TOP w0.305: v1(10.38,30.73) 10.92,31.27 C108.1 12.99,30.36 11.93,29.31 U10.6
  L3_PWR w0.305: v1(10.38,30.73) 10.38,30 8.68,28.3 8.68,27.69 7.64,26.64 7.64,22.48 8.61,21.51 8.61,19.25 8.56,19.2 ; v1(7.46,18.75) 7.92,19.2
  L3_PWR w0.406: v1(38.48,12.47) 41.8,15.8 41.8,31.7 39.92,33.58 38.96,33.58 v1(38.91,33.63)
  BOTTOM w0.254: U5.4 17.63,20.08 18.35,19.37 R10.1
  BOTTOM w0.305: C12.1 32.44,5.6 32.06,5.98 C10.1 R6.1
  BOTTOM w0.406: v1(38.91,33.63) 34.37,33.63 34.16,33.83 31,33.83 30.94,33.89
  BOTTOM w0.508: 30.94,33.89 J3.36 J3.34
  vias: v1(6.7,19.56) v1(6.68,18.75) v1(7.49,19.53) v1(22.37,2.13) v1(22.4,1.35) v1(23.19,2.13) v1(23.19,1.35)
VCC_12V: length 3
  BOTTOM w0.254: U2.5 36.39,8.79 36.13,9.05 R4.1
  vias: v1(39.47,6.81) v1(40.08,8.2) v1(40.08,7.42) v1(40.69,6.81) v1(41.14,7.8) v1(42.06,7.8)
VCC_DDR: length 15.9
  TOP w0.127: U6.F5 v1(33.97,27.08) ; U6.E8 v1(34.62,24.48) U6.E9 ; U6.E11 v1(34.62,23.18) U6.E10 ; U6.F9 v1(33.97,24.48) ; U6.E12 v1(34.62,21.88) ; U6.F7 v1(33.97,25.78) U6.F6 ; U6.E7 v1(34.62,25.78) U6.E6 ; U6.F12 v1(33.97,21.88) ; U6.F10 v1(33.97,23.18) U6.F11
  BOTTOM w0.254: v1(33.97,27.08) 34.46,27.57 34.46,27.58 34.83,27.95 35.46,27.95 36.39,28.88 C40.2 36.39,29.86 R15.2 C41.1
  BOTTOM w0.305: R7.2 C9.1 34.35,18.17 34.78,18.6 C15.1
VDDMSC0: length 15.6
  TOP w0.305: J2.4 v1(29.32,12.85)
  BOTTOM w0.203: C94.1 29.65,13.61 R30.1 R33.1 R32.1
  BOTTOM w0.254: R29.1 27.14,12.87 27.15,12.85 ; R31.1 23.81,13.25 24.71,12.34 26.64,12.34 27.15,12.85 ; 27.15,12.85 v1(29.32,12.85)
  BOTTOM w0.305: Q1.3 28.85,15.57 29.29,15.13 C93.1 C94.1 29.29,12.88 v1(29.32,12.85)
ACTA: length 3.6
  TOP w0.102: J5.6 10.22,17.97 10.51,18.26 10.51,18.73 R74.2 R77.1
BOOTSEL0: length 20.2
  TOP w0.102: SW1.2 33.19,35.94 37.11,35.94 40.61,32.44 40.61,29.08 40.98,28.72 R55.1 40.98,27.14 39.77,25.93 39.77,24.97 39.37,24.56 37.51,24.56 37.11,24.16 U6.A9
BOOTSEL1: length 2.8
  TOP w0.102: U6.B9 36.63,24.54 37.14,24.54 R59.2 R56.1
CIM_MCLK: length 10.2
  TOP w0.102: R67.1 34.44,31.7 34.21,31.93 v1(34.21,31.95)
  BOTTOM w0.102: J3.28 26.77,33.22 26.97,33.02 27.91,33.02 28.49,32.44 28.49,32.05 29.43,31.11 31.14,31.11 31.97,31.95 v1(34.21,31.95)
CLK_CTL: length 1.5
  TOP w0.102: R92.2 20.25,17.68 U8.12
CORE_FB: length 3.1
  BOTTOM w0.305: C23.1 R63.1 R64.1 17.24,22.67 17.24,22.67 U5.5
CSI_VCC08: length 3.4
  TOP w0.178: 28.7,29.26 29.1,28.86 U6.N2
  TOP w0.203: v1(28.77,29.9) 28.8,29.87 28.8,29.74 28.7,29.64 28.7,29.26
  BOTTOM w0.203: C85.1 C84.1 FB8.1
  BOTTOM w0.254: C85.1 v1(28.77,29.9)
CSI_VCC18: length 3.4
  TOP w0.254: v1(31.3,27.8) U6.K3
  BOTTOM w0.254: FB9.1 32.32,30.22 C86.1 C29.1 32.22,28.37 32.03,28.37 31.5,27.85 31.48,27.85 31.43,27.8 v1(31.3,27.8)
DDR_VREF: length 5.4
  TOP w0.254: U6.E5 v1(34.62,27.08)
  BOTTOM w0.254: R15.1 37.27,29.72 R17.2 C42.2 37.26,27.95 C40.1 35.97,27.53 35.07,27.53 v1(34.62,27.08)
DDRPLL: length 3.3
  TOP w0.254: v1(36.95,24.99) 36.43,24.99 U6.B8
  BOTTOM w0.254: FB1.1 37.65,23.17 C54.1 C64.1 37.58,24.99 v1(36.95,24.99)
DVP_D0: length 17.9
  TOP w0.102: 30.7,29.46 30.7,29.01 U6.L2
  TOP w0.104: v1(19.02,35.59) 19.2,35.59 19.71,36.09 21.28,36.09 22.12,35.26 22.12,34.87 23.59,33.4 27.73,33.4 30.7,30.43 30.7,29.46
  BOTTOM w0.104: v1(19.02,35.59) 18.54,35.59 18.27,35.85 J3.11
DVP_D1: length 16.6
  TOP w0.102: U6.L1 30.37,29.38 30.37,30.25
  TOP w0.104: 30.37,30.25 30.37,30.4 27.63,33.15 23.49,33.15 21.87,34.77 21.87,34.8 21.84,34.82 21.84,35.18 21.18,35.84 19.83,35.84 19.45,35.46 19.45,34.98 v1(19.4,34.92)
  BOTTOM w0.104: J3.12 18.77,34.57 19.12,34.92 v1(19.4,34.92)
DVP_D2: length 14.1
  TOP w0.104: U6.N1 29.16,29.42 29.16,30.15 27.17,32.13 23.06,32.13 21.26,33.93 20.7,33.93 19.83,34.8 v1(19.83,35.31)
  BOTTOM w0.104: J3.13 19.27,35.87 v1(19.83,35.31)
DVP_D3: length 15
  TOP w0.104: U6.M3 29.41,28.39 29.41,30.25 27.28,32.38 23.16,32.38 21.36,34.19 20.85,34.19 20.39,34.65 20.39,34.95 v1(20.32,35.03)
  BOTTOM w0.104: v1(20.32,35.03) 20.19,35.03 19.77,34.61 J3.14
DVP_D4: length 13.4
  TOP w0.104: U6.M2 29.75,30.27 27.38,32.64 23.24,32.64 21.05,34.82 20.9,34.82 v1(20.84,34.89)
  BOTTOM w0.104: J3.16 20.84,33.96 v1(20.84,34.89)
DVP_D5: length 15.1
  TOP w0.104: v1(20.95,35.46) 21,35.46 21.56,34.9 21.56,34.7 23.36,32.89 27.53,32.89 29.99,30.43 29.99,28.91 30.07,28.83 30.07,28.38 U6.L3
  BOTTOM w0.104: v1(20.95,35.46) 20.95,35.46 20.95,35.61 21.27,35.93 J3.17
DVP_D6: length 15.7
  TOP w0.102: U6.H2 32.23,28.82
  TOP w0.104: 32.23,28.82 32.23,29.92 32.05,30.1 32.05,31.32 30.02,33.35 28.24,33.35 27.94,33.66 23.75,33.66 22.63,34.77 22.63,34.98 v1(22.55,35.05)
  BOTTOM w0.104: J3.18 21.77,34.68 22.25,35.15 22.45,35.15 v1(22.55,35.05)
